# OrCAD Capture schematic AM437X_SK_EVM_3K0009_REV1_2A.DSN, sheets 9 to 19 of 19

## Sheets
9 Pg03: Processor Power: size C
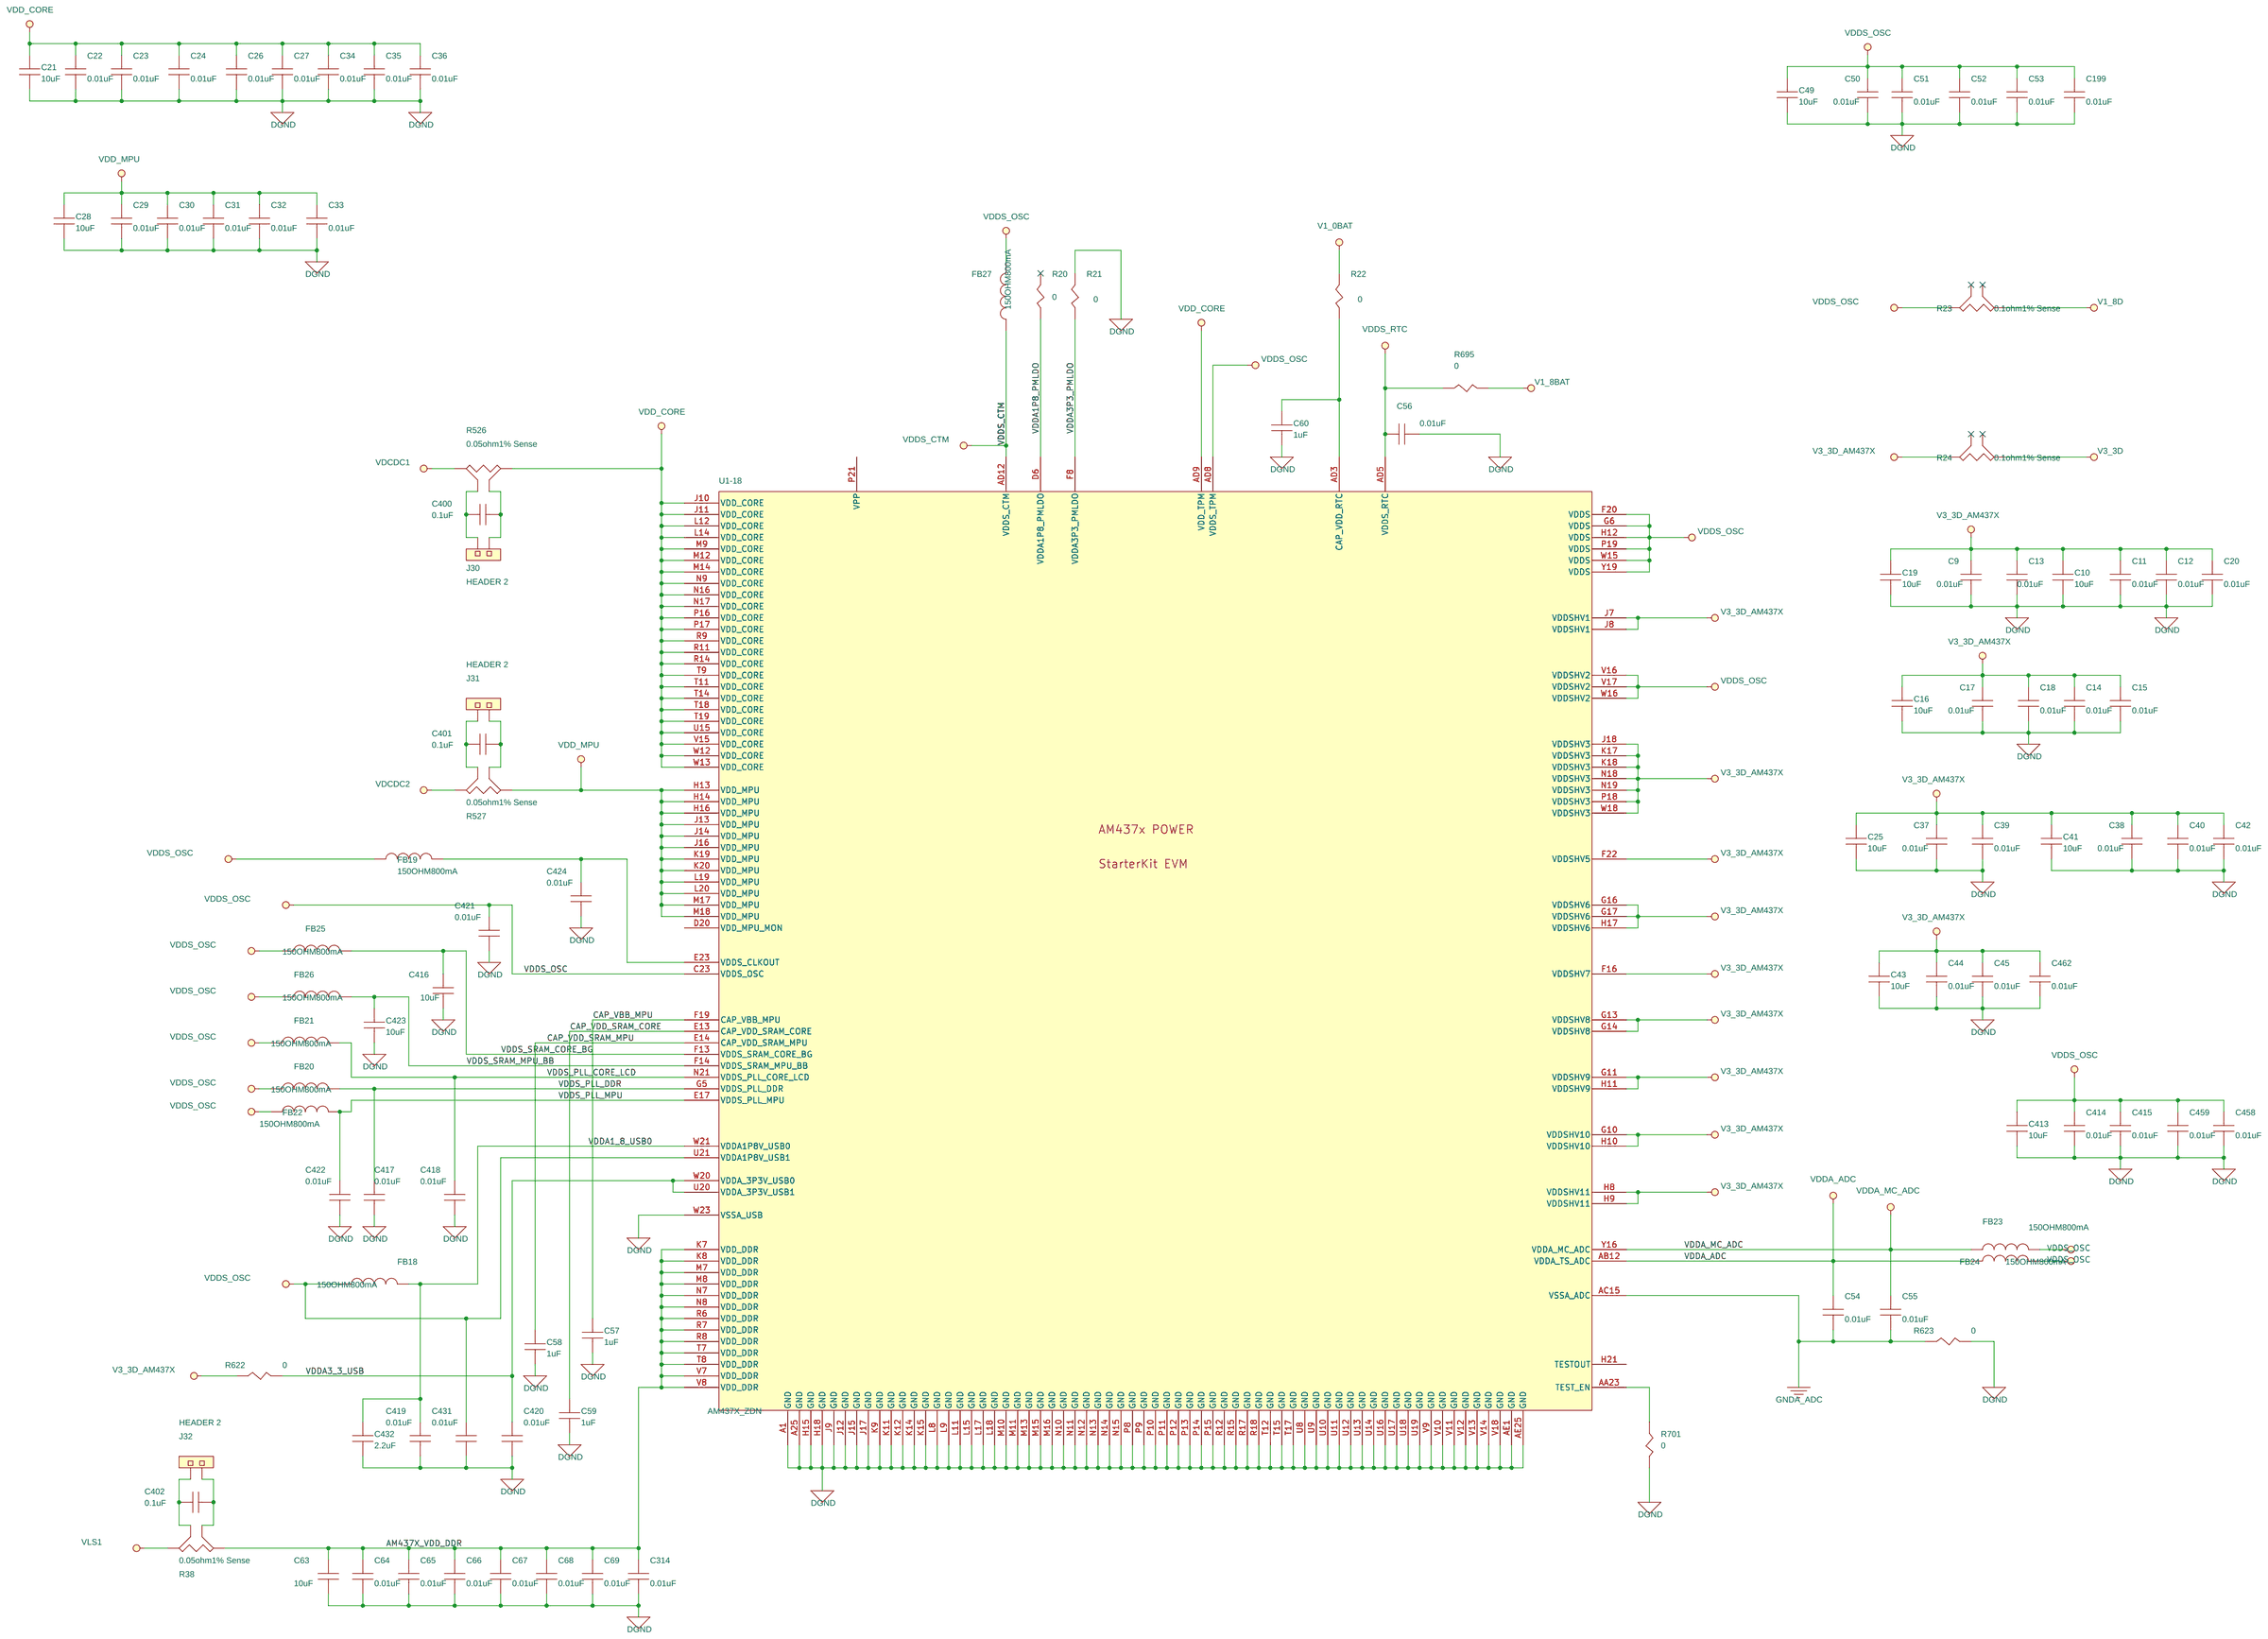
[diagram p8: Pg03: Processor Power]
10 Pg14: USB Port #1: size C
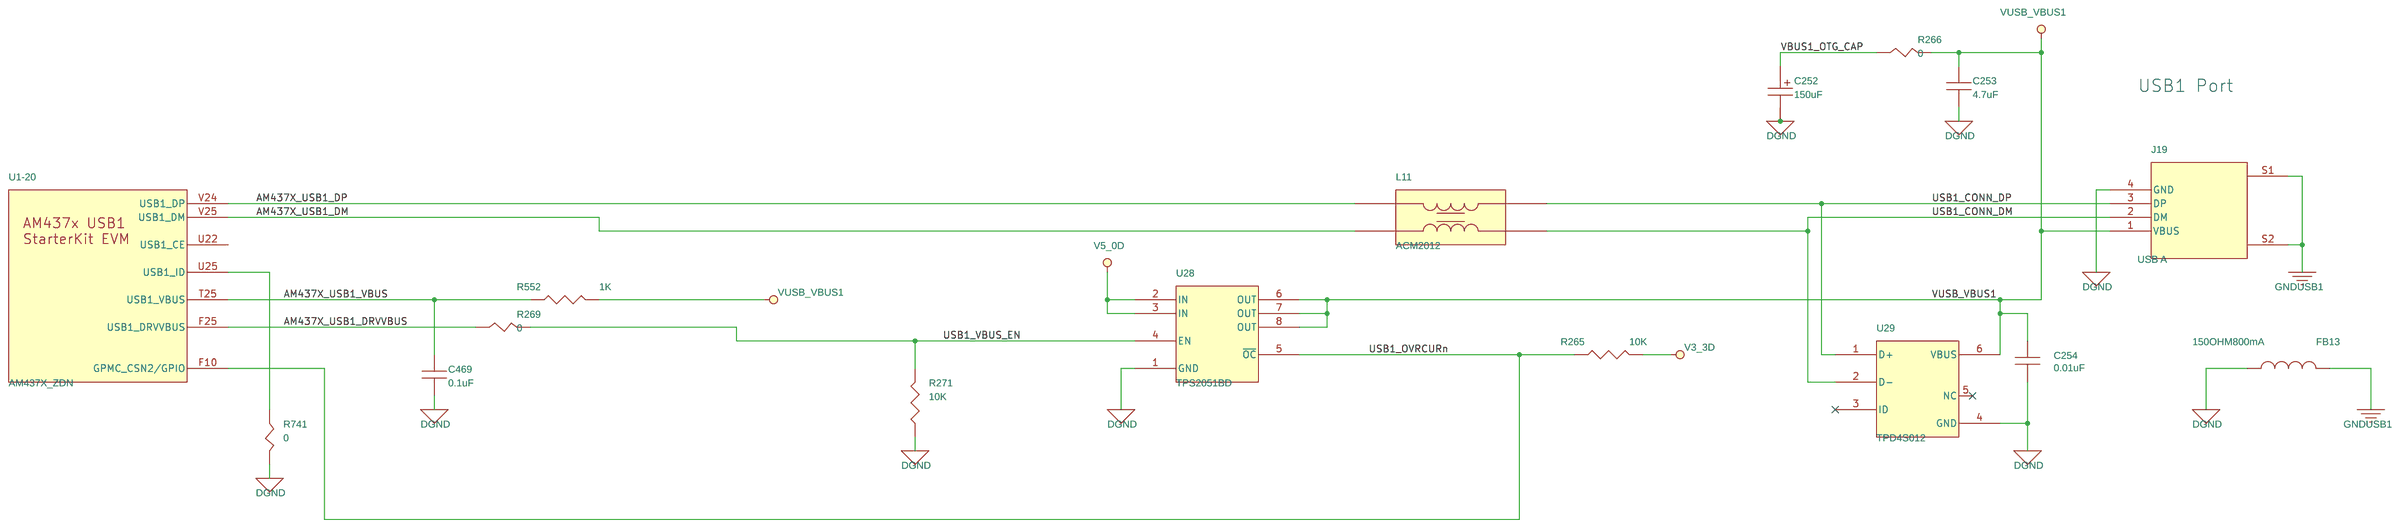
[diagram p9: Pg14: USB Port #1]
11 Pg13: USB Port #0: size C
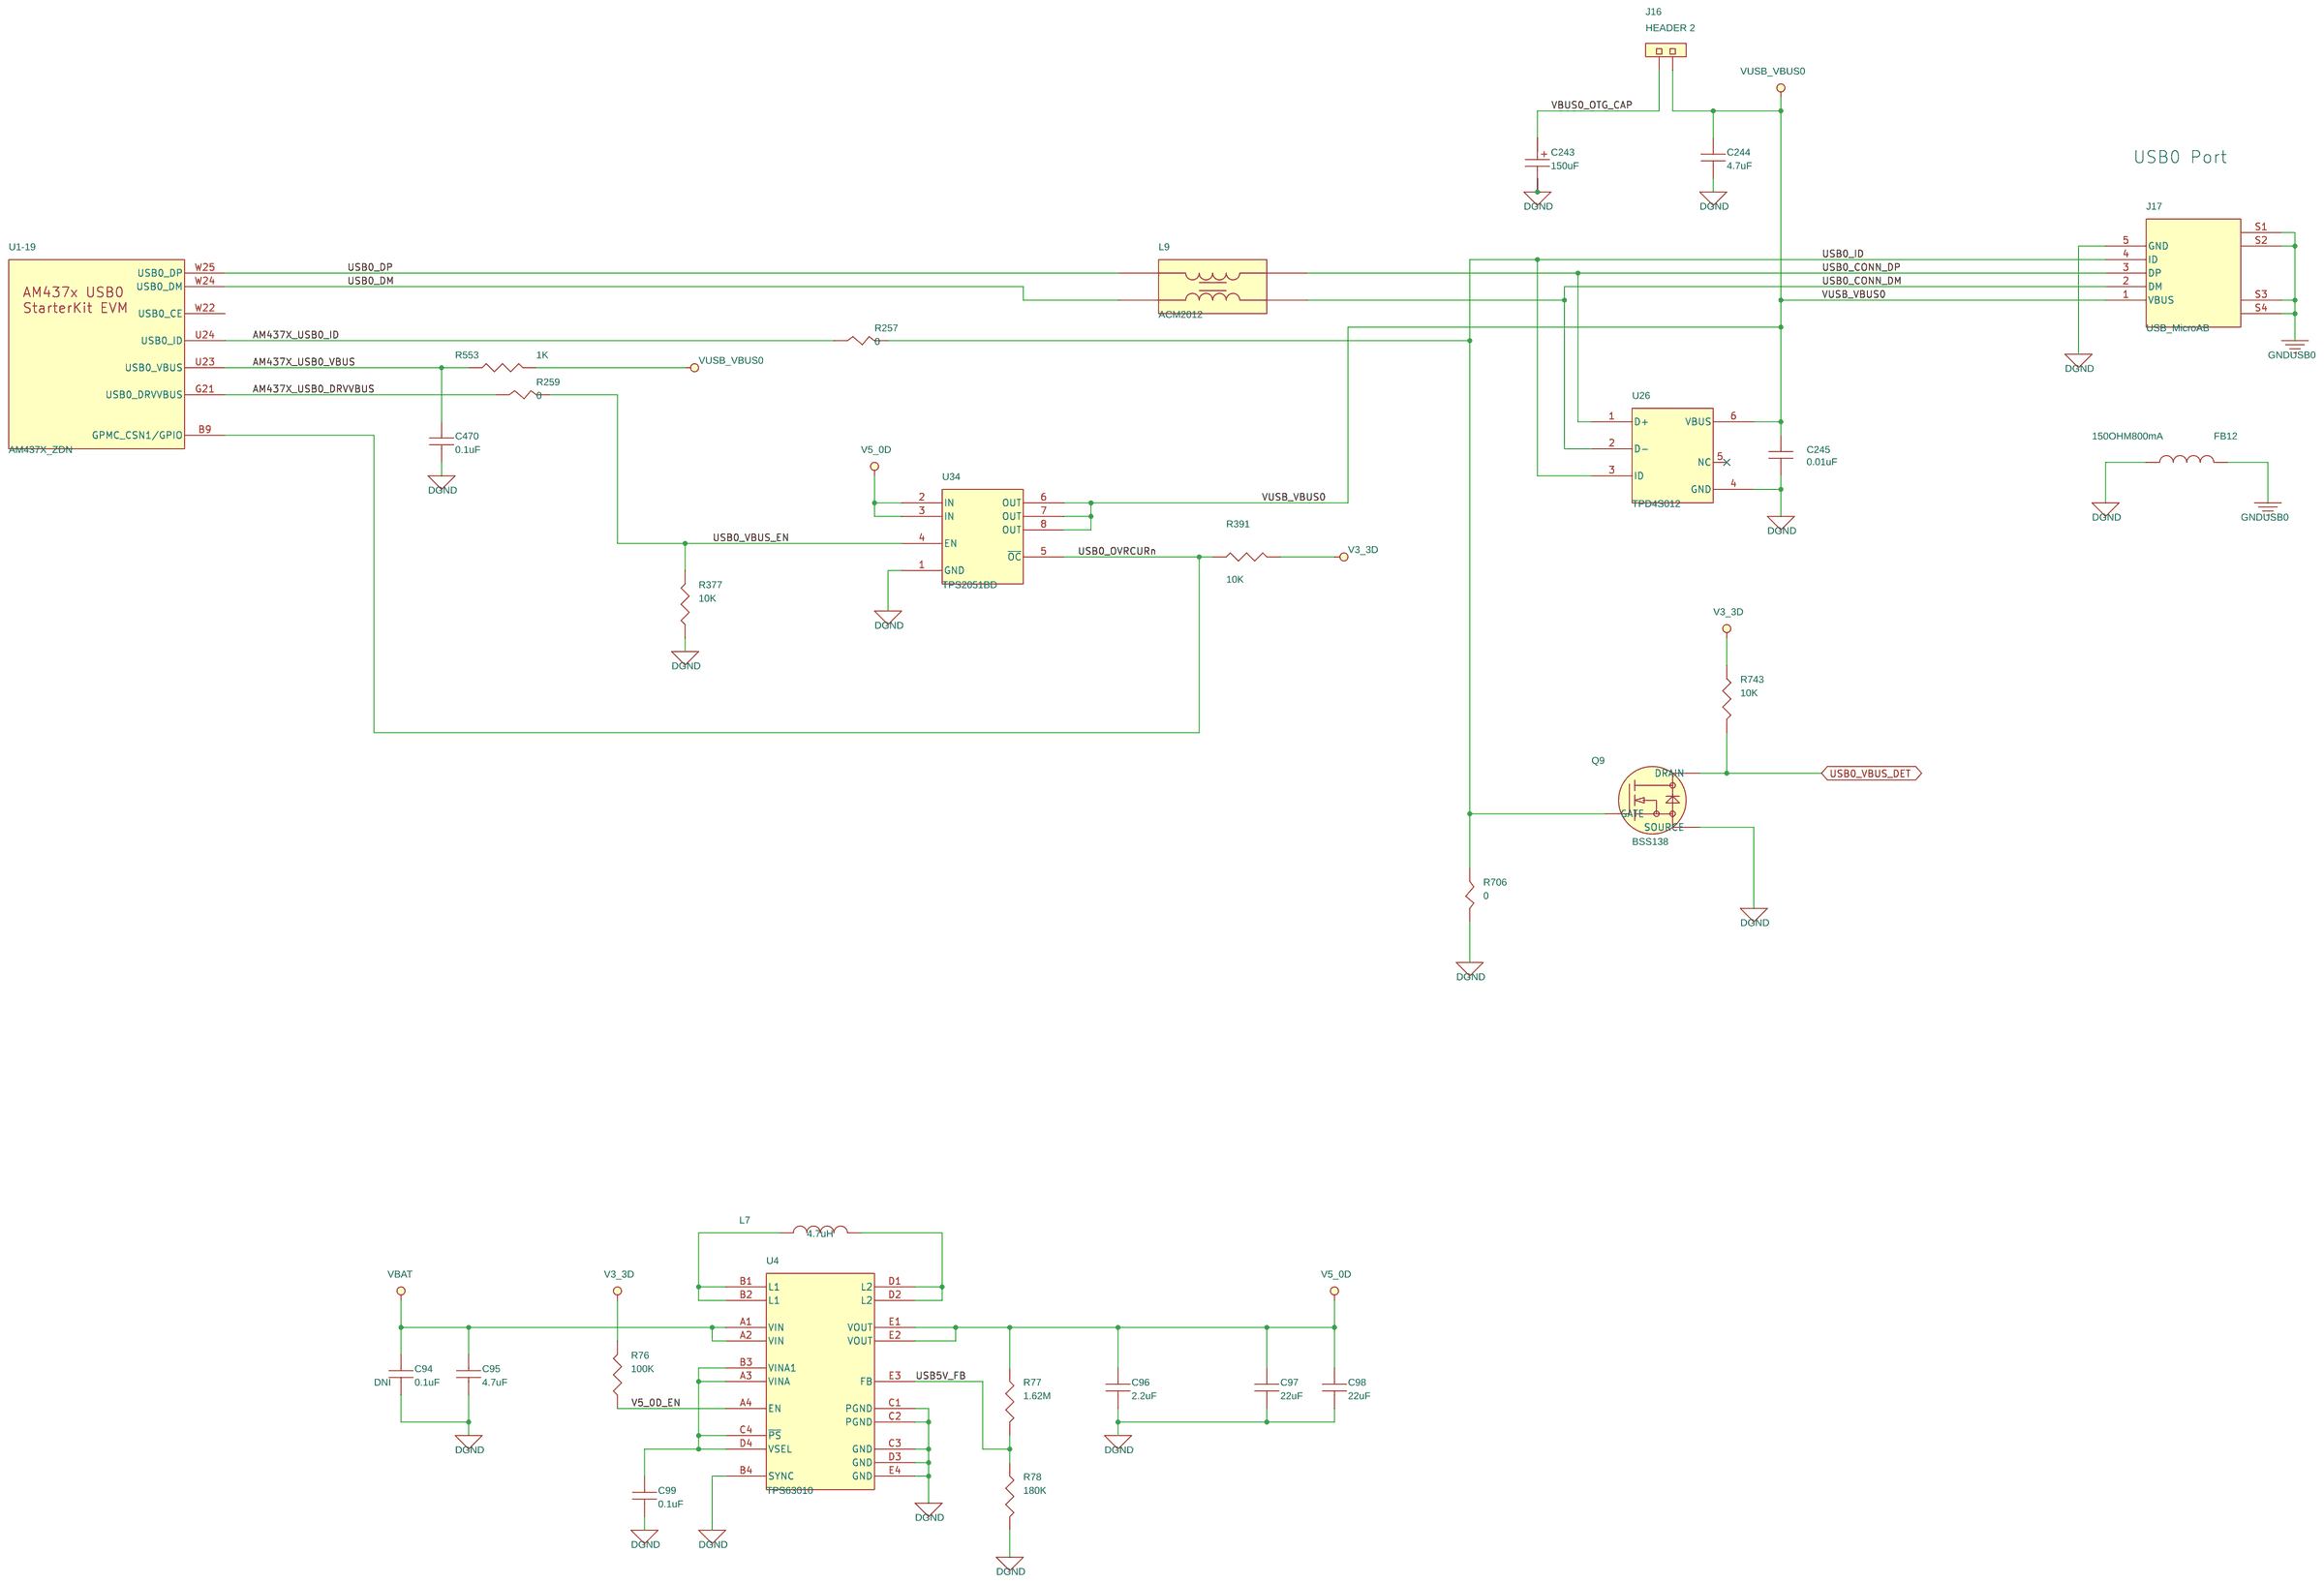
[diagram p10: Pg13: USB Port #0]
12 Pg17: Keypad/LED's: size C
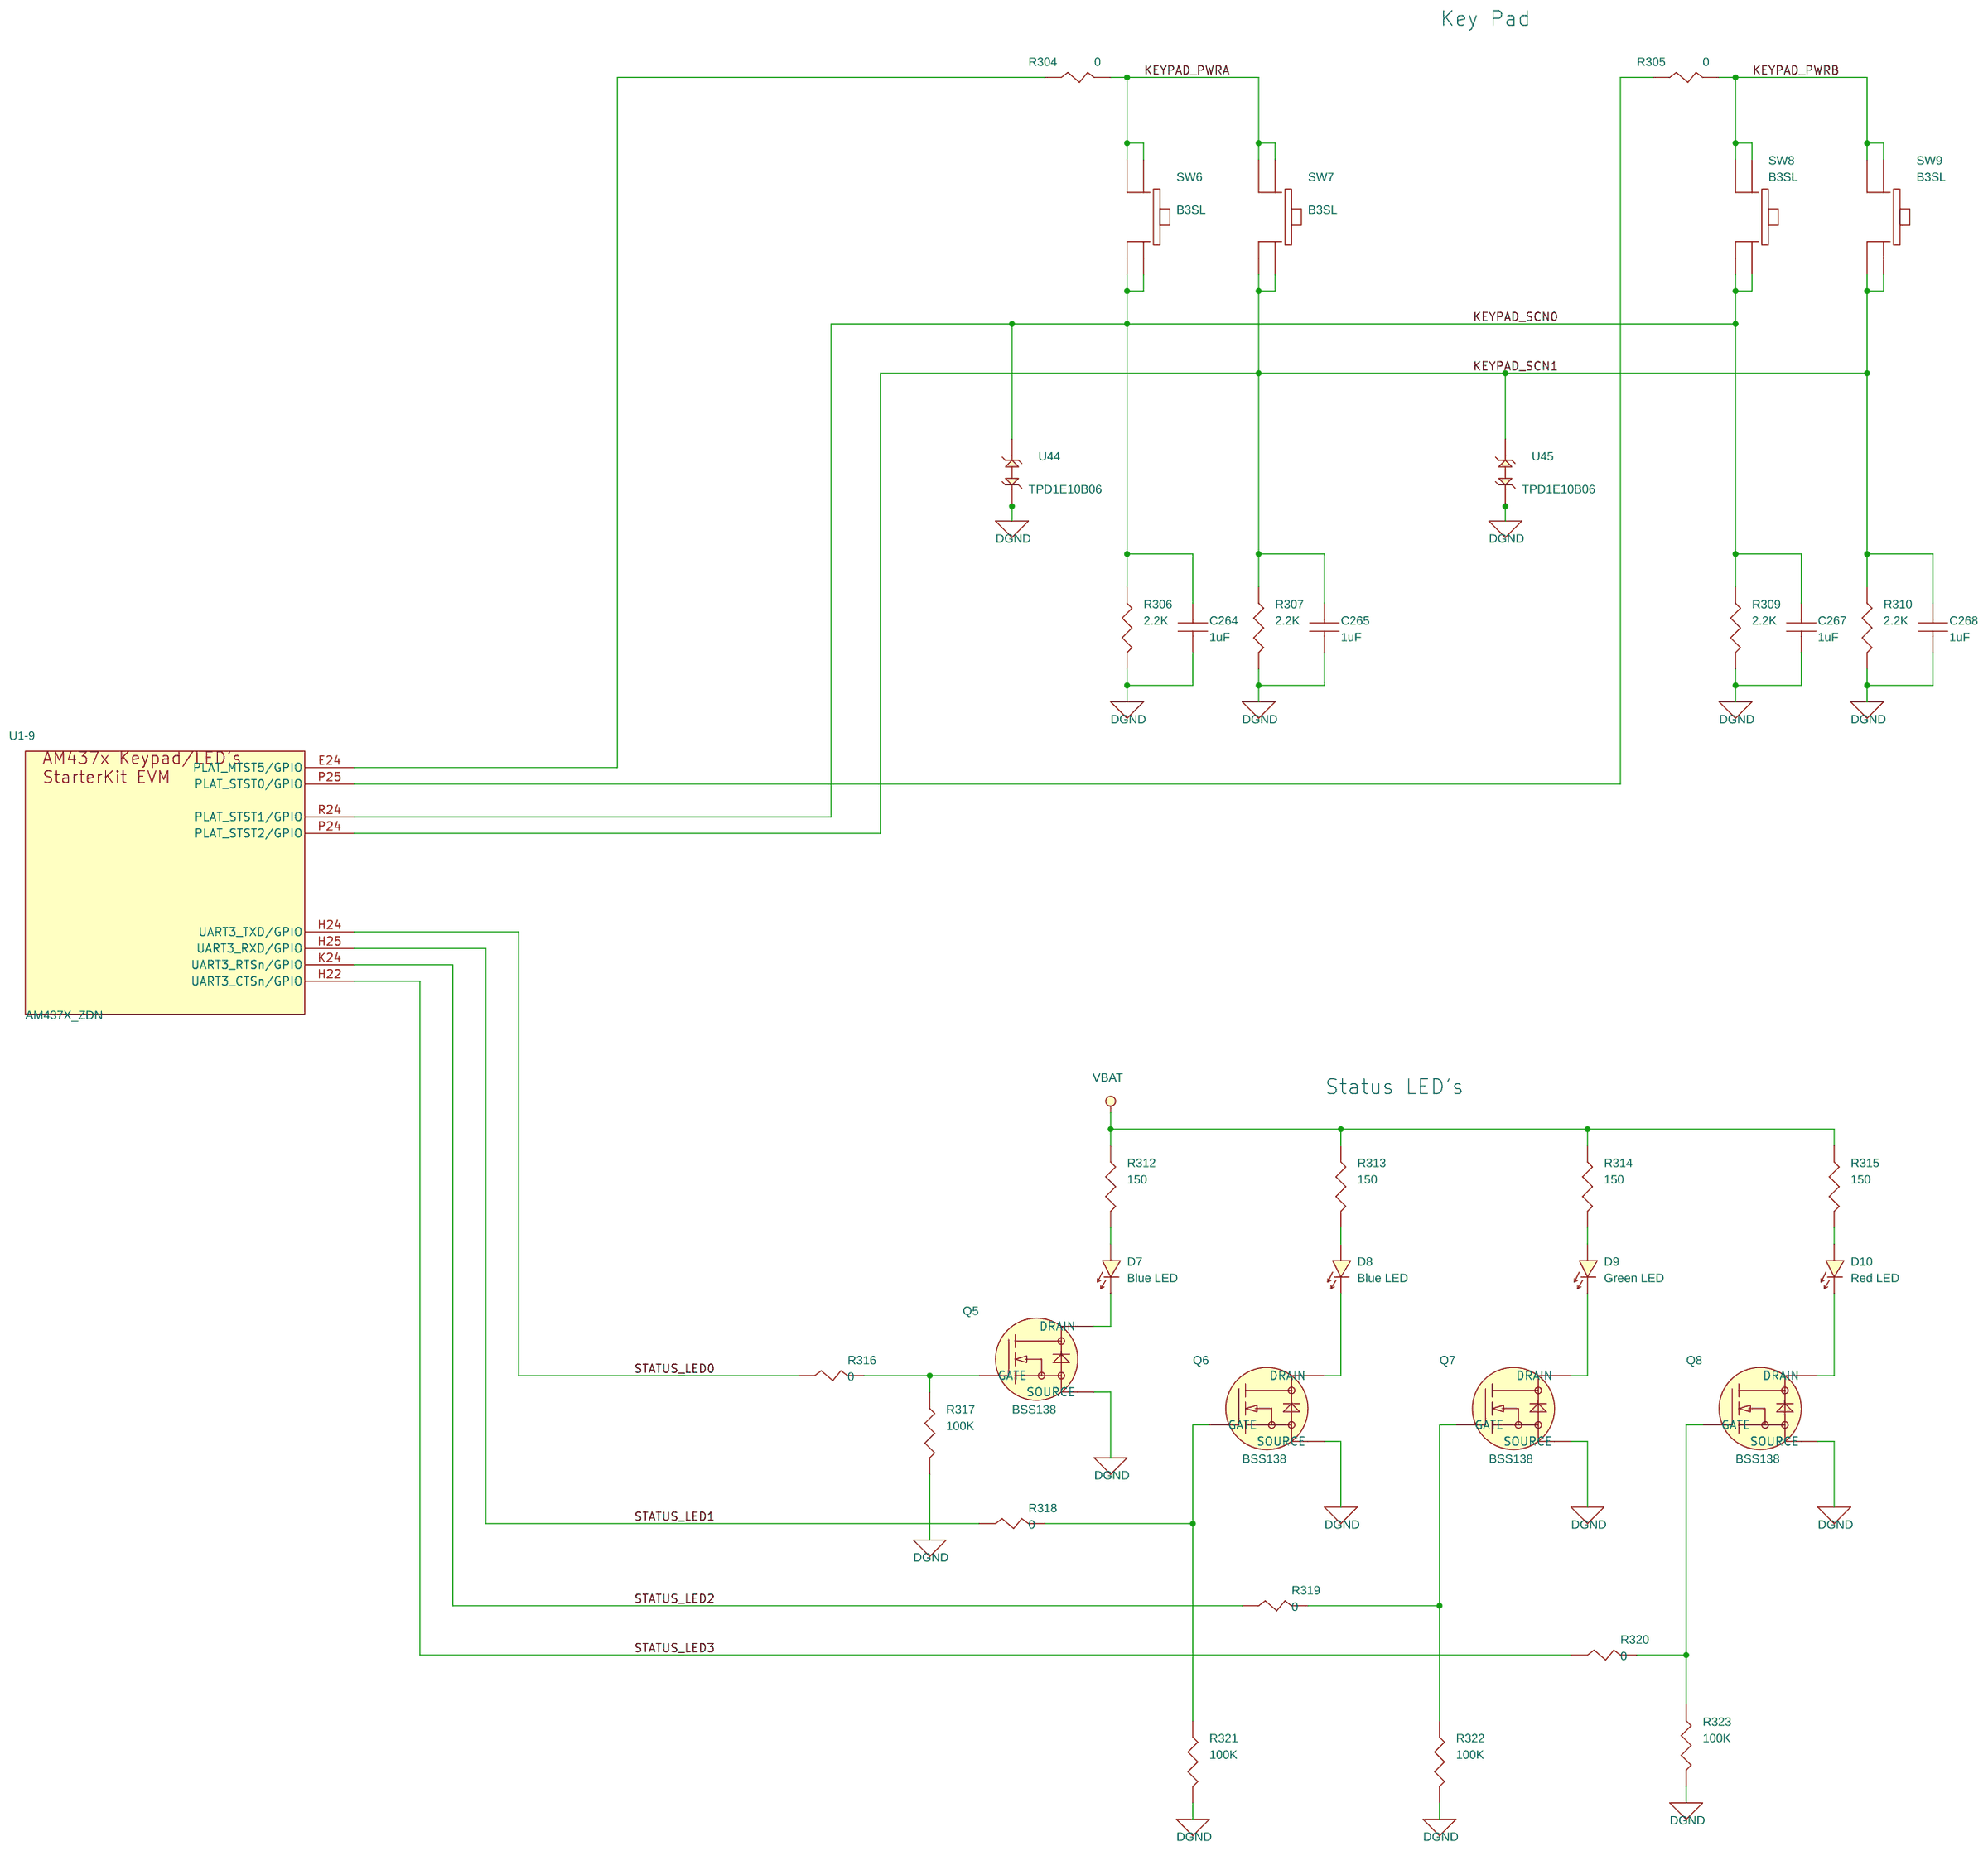
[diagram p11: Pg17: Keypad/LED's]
13 Pg07: SDMMC0 Interface: size C
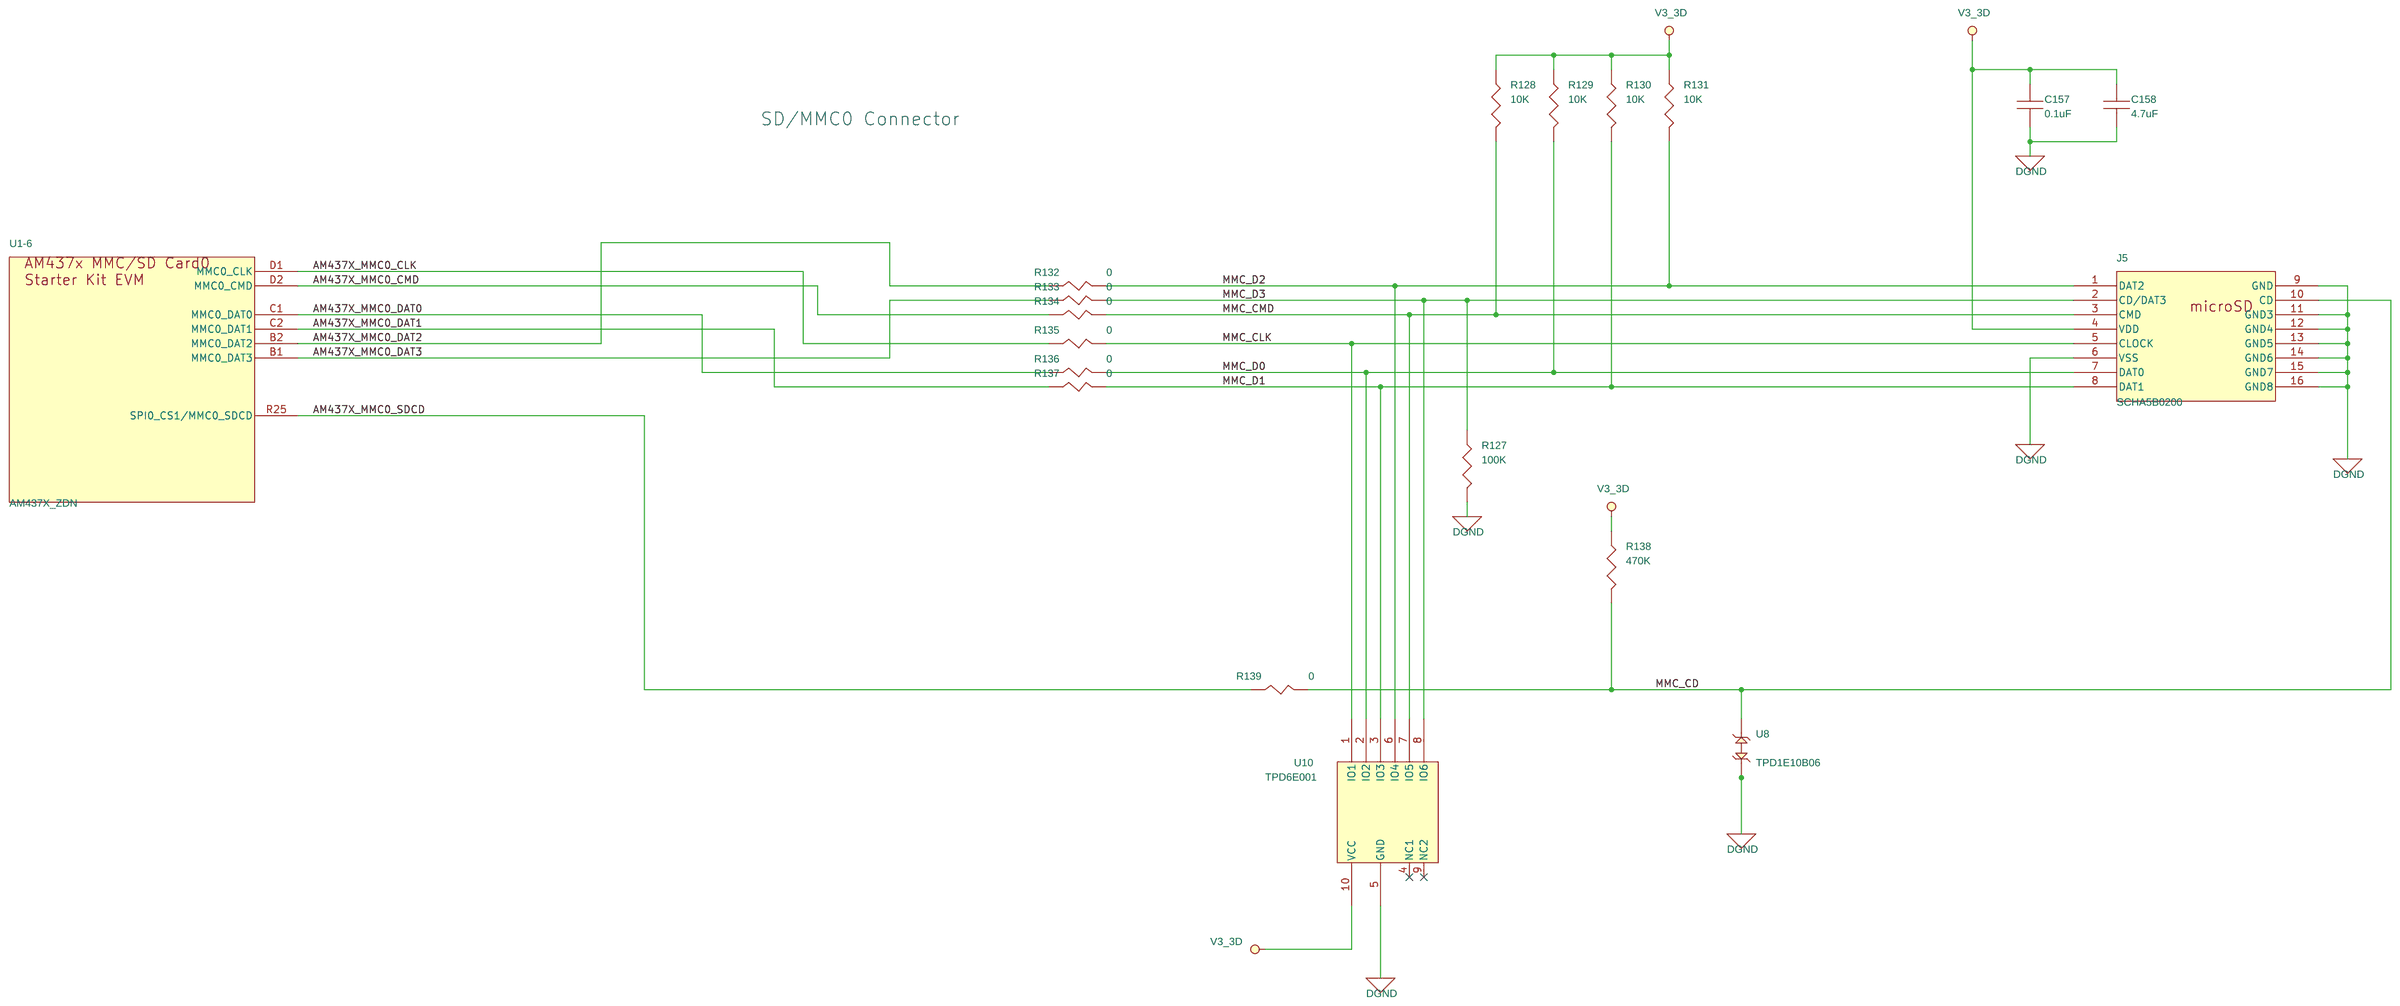
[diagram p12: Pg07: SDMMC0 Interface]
14 Pg11: LCD/Touchscreen: size C
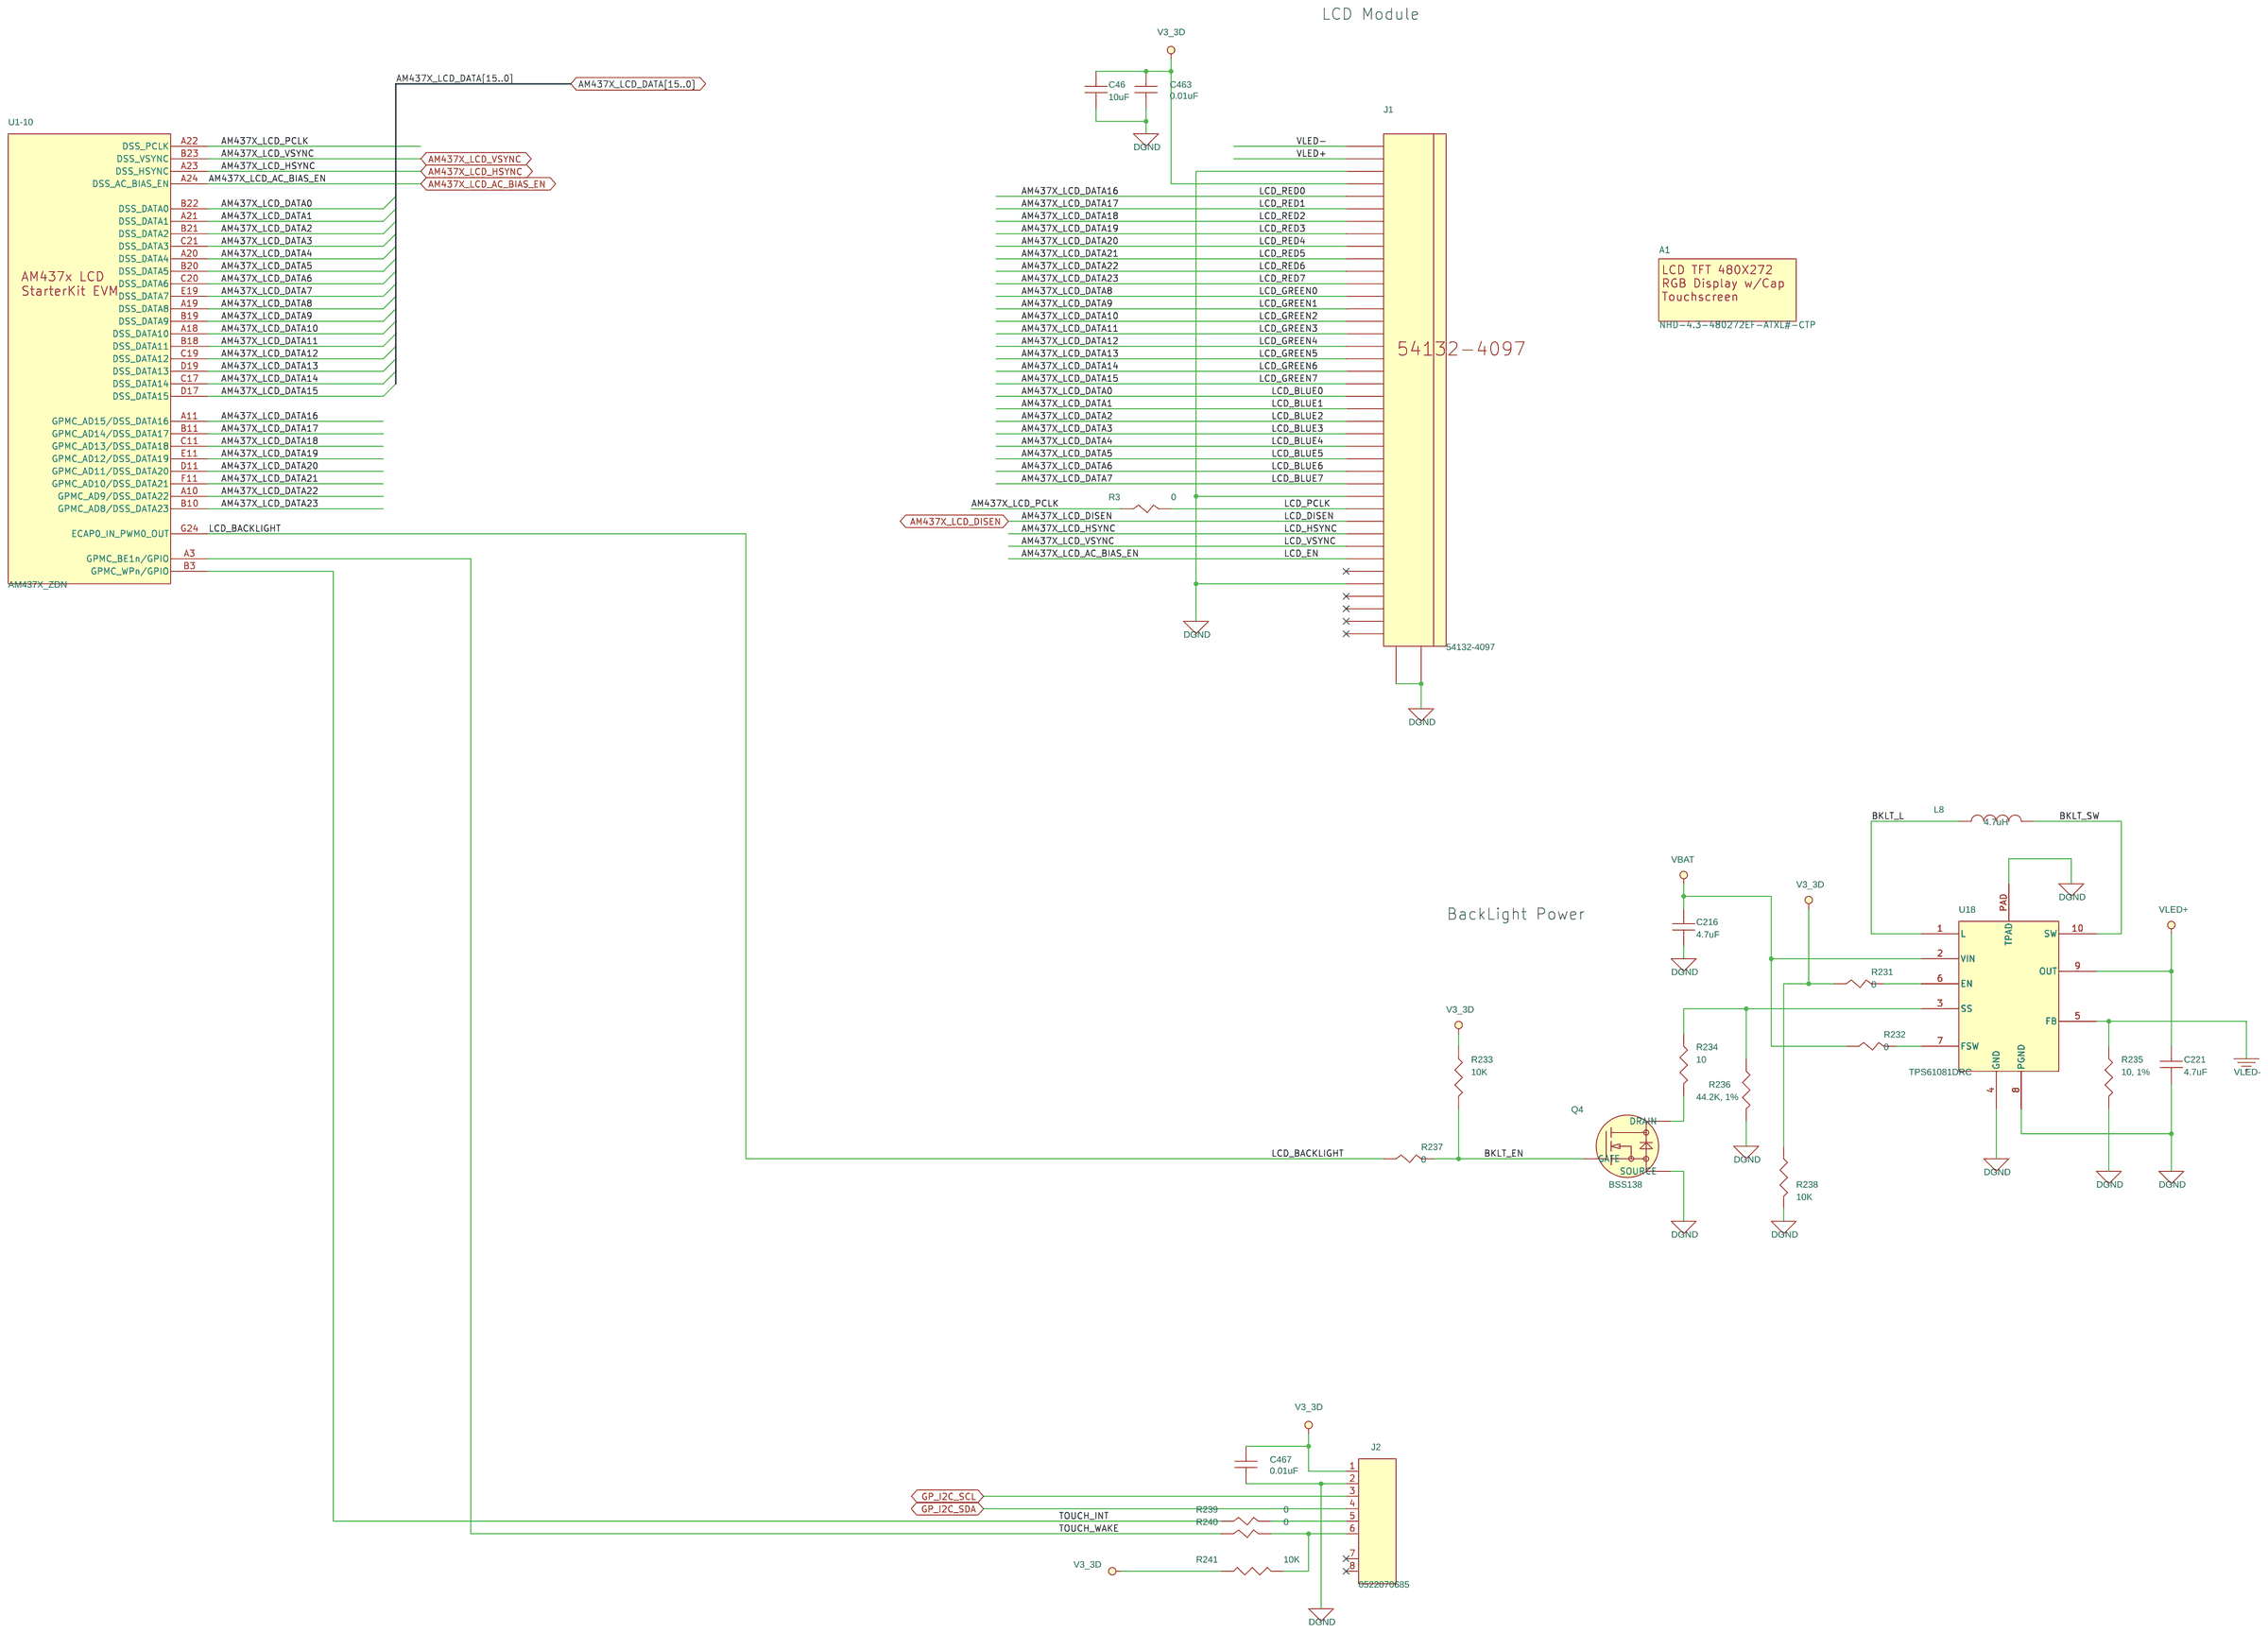
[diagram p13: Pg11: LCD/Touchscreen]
15 Pg02: Processor subsystem: size C
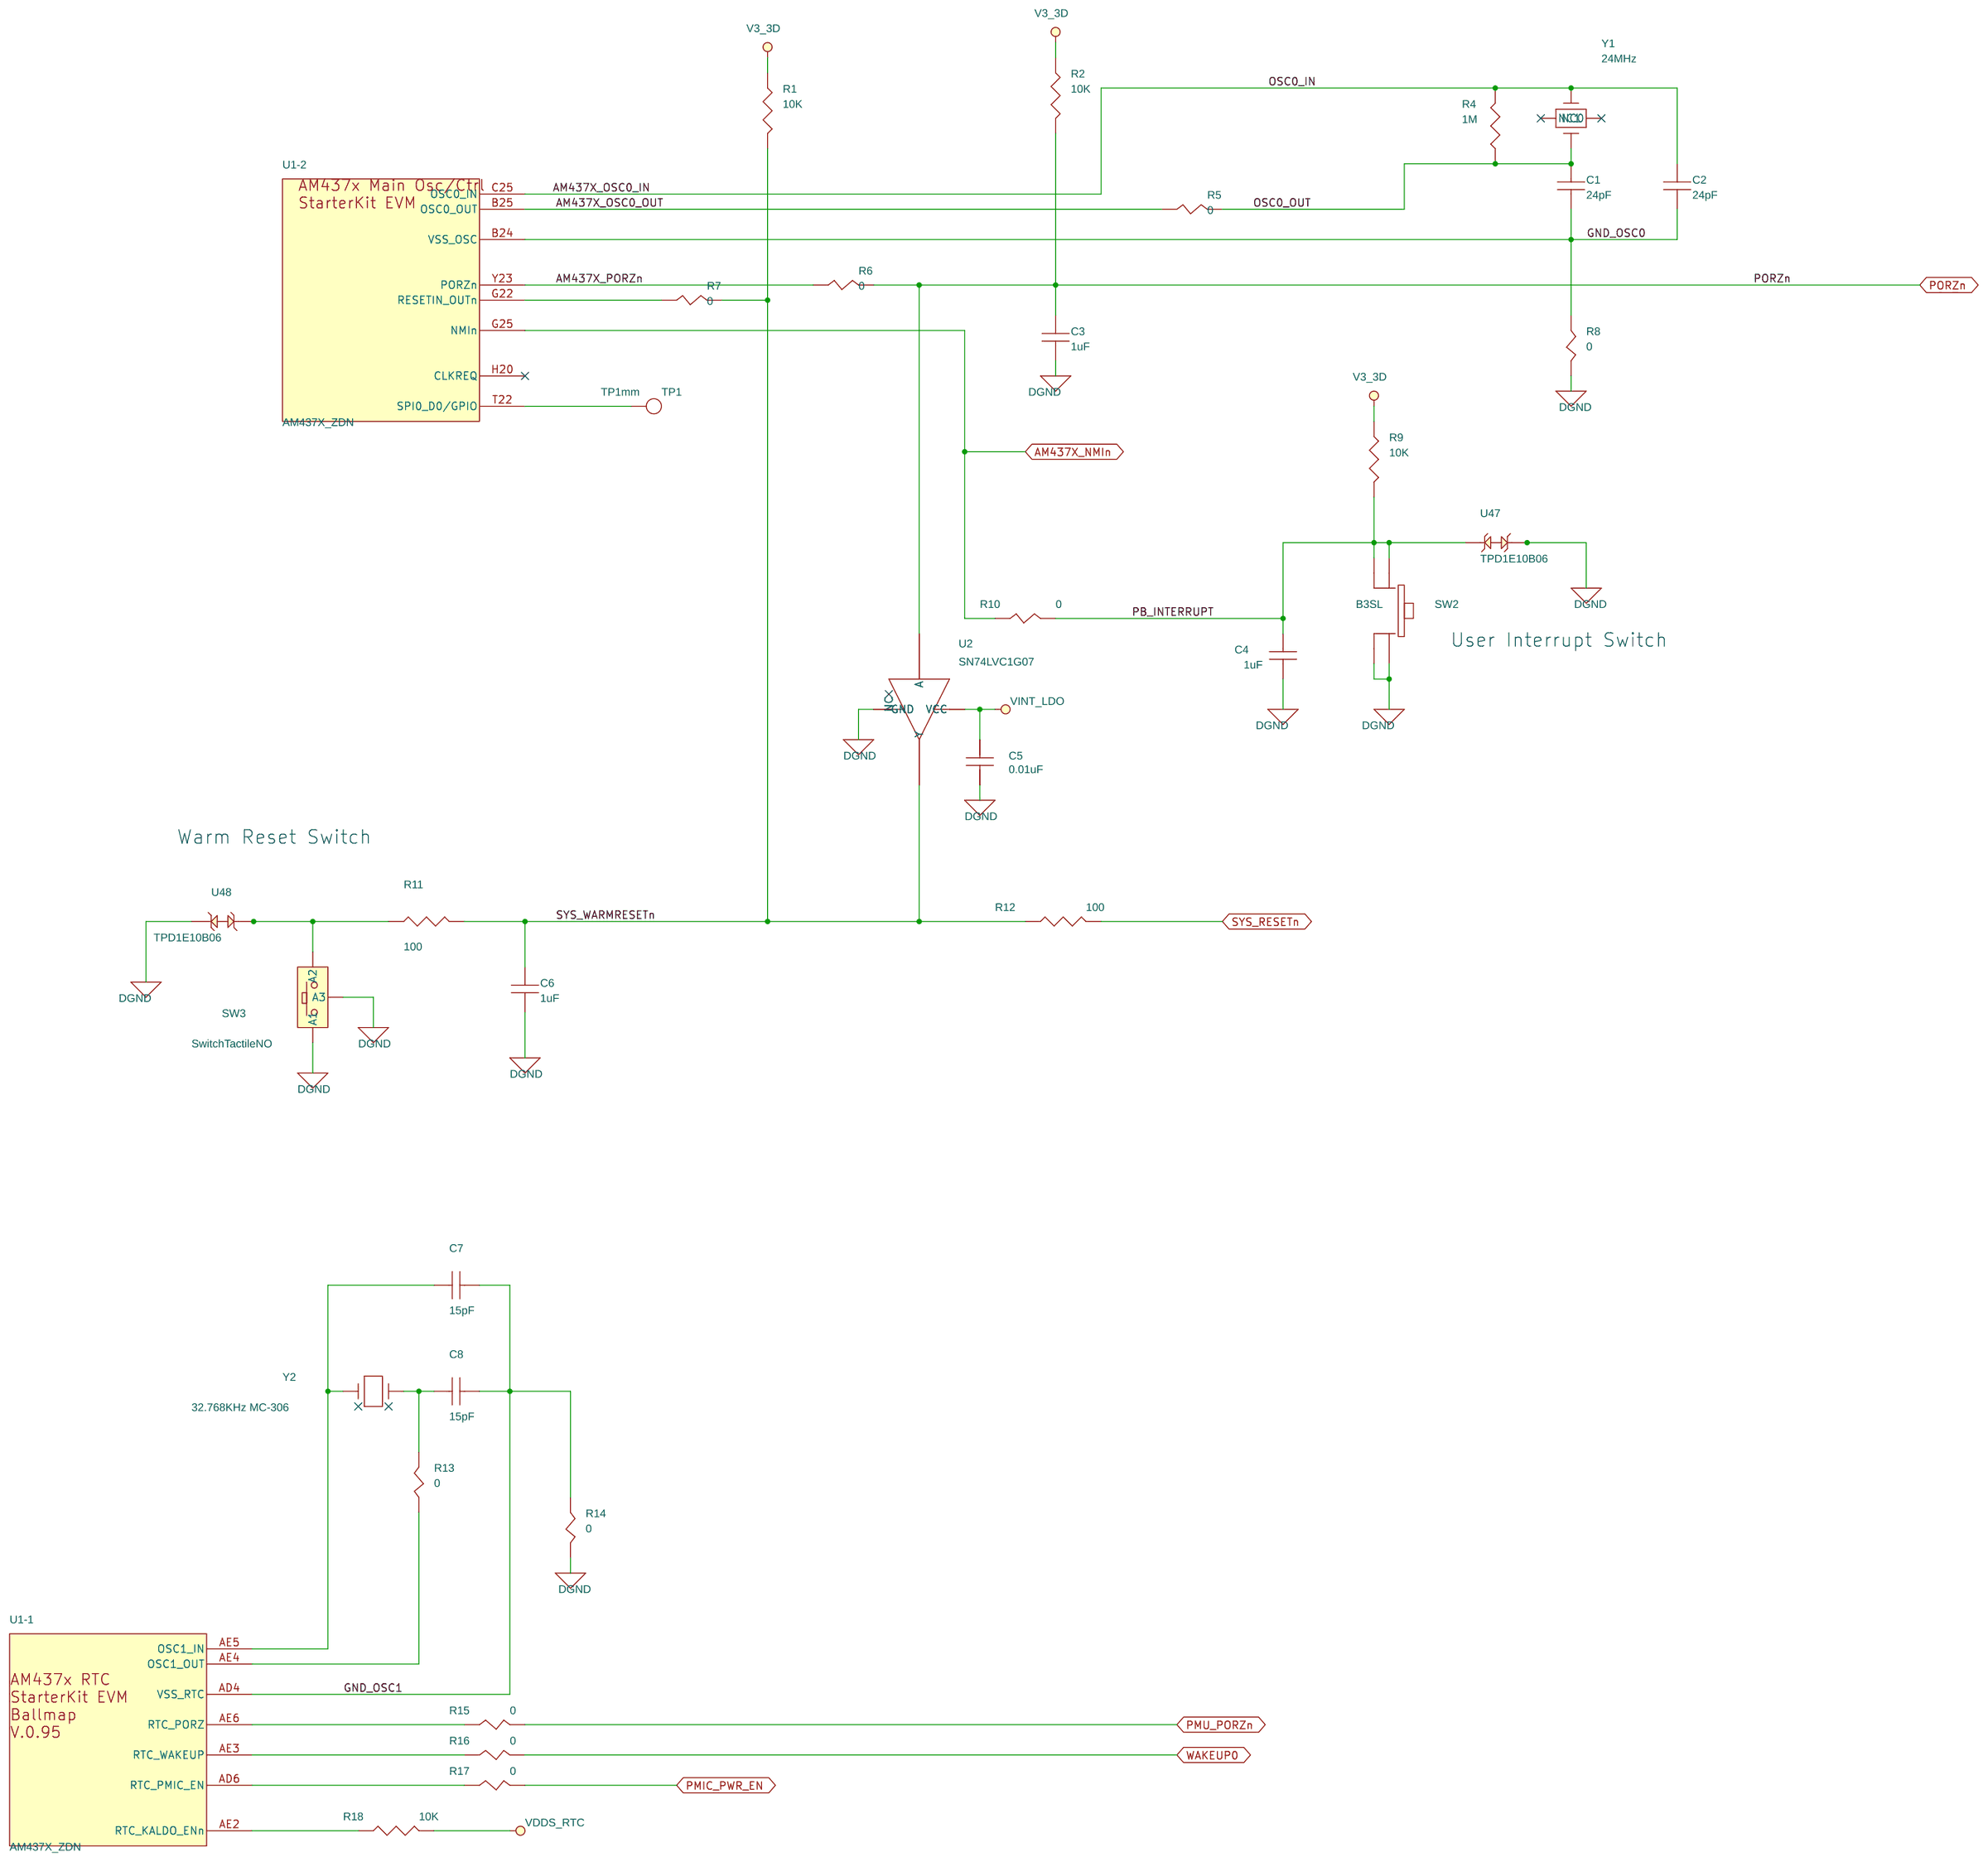
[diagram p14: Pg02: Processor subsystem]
16 Pg15: Unused pins/GPIO: size C
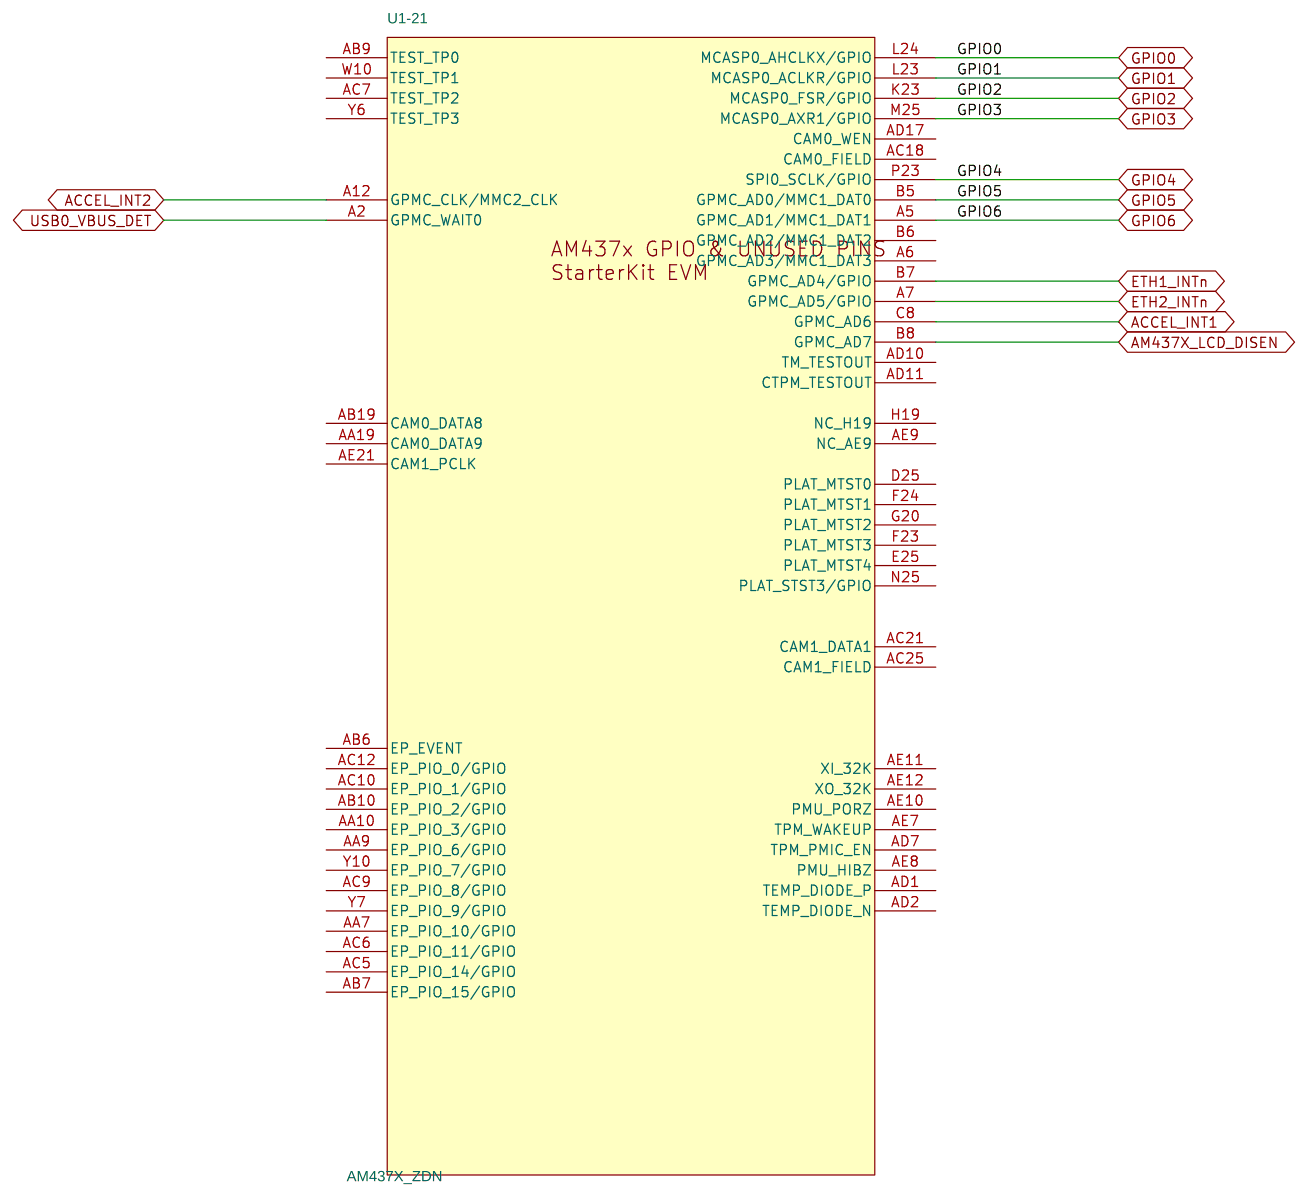
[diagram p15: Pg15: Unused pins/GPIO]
17 Pg05: QSPI NOR Flash Memory: size C
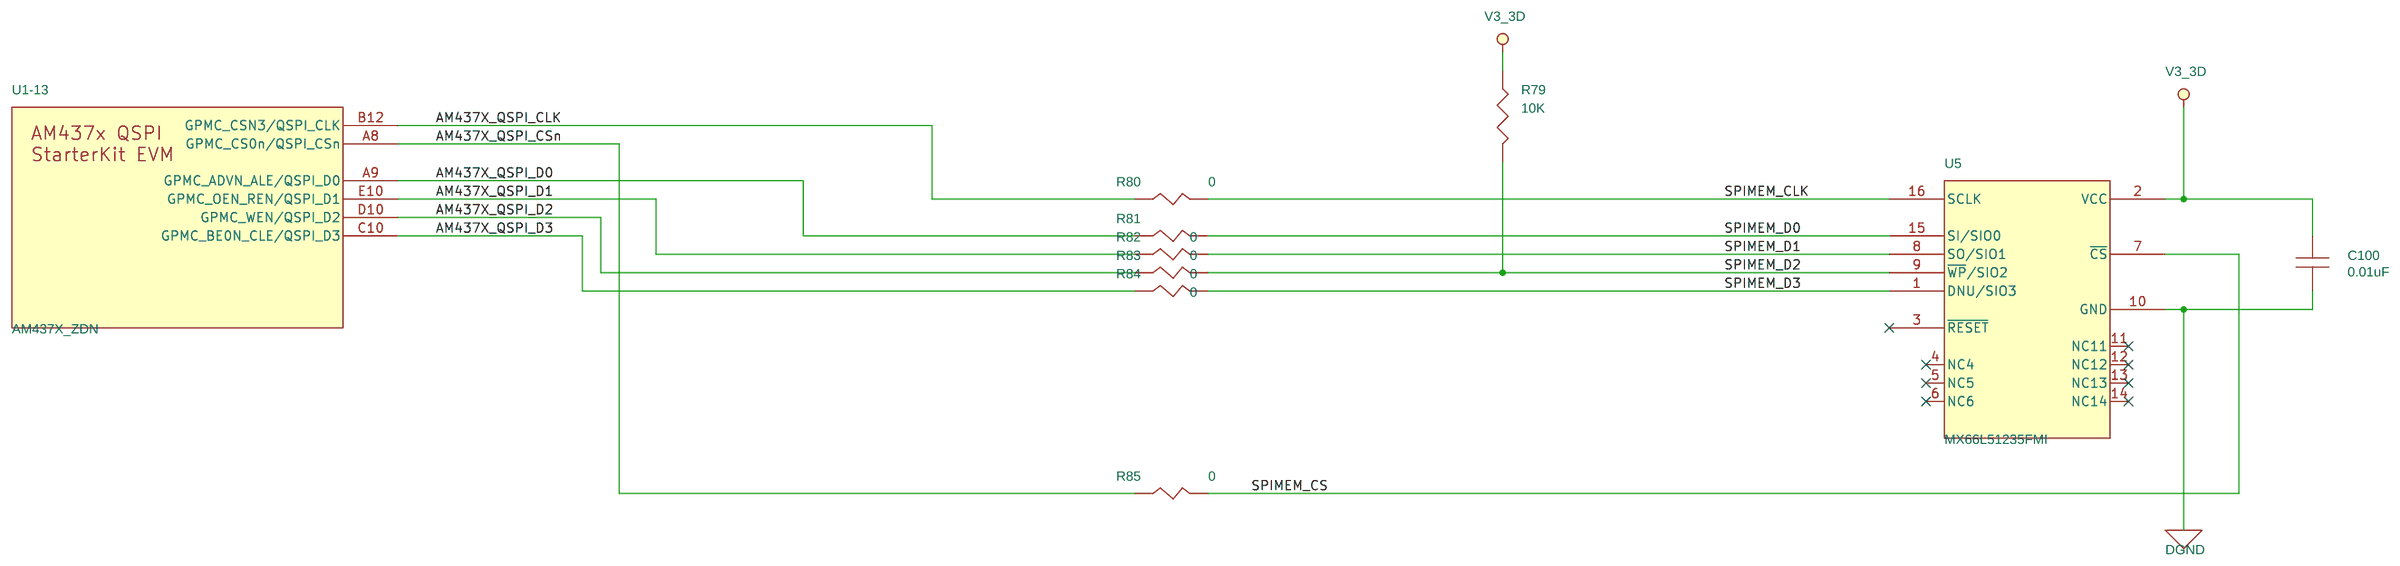
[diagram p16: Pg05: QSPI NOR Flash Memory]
18 Pg04: Power Supply - PMIC: size C
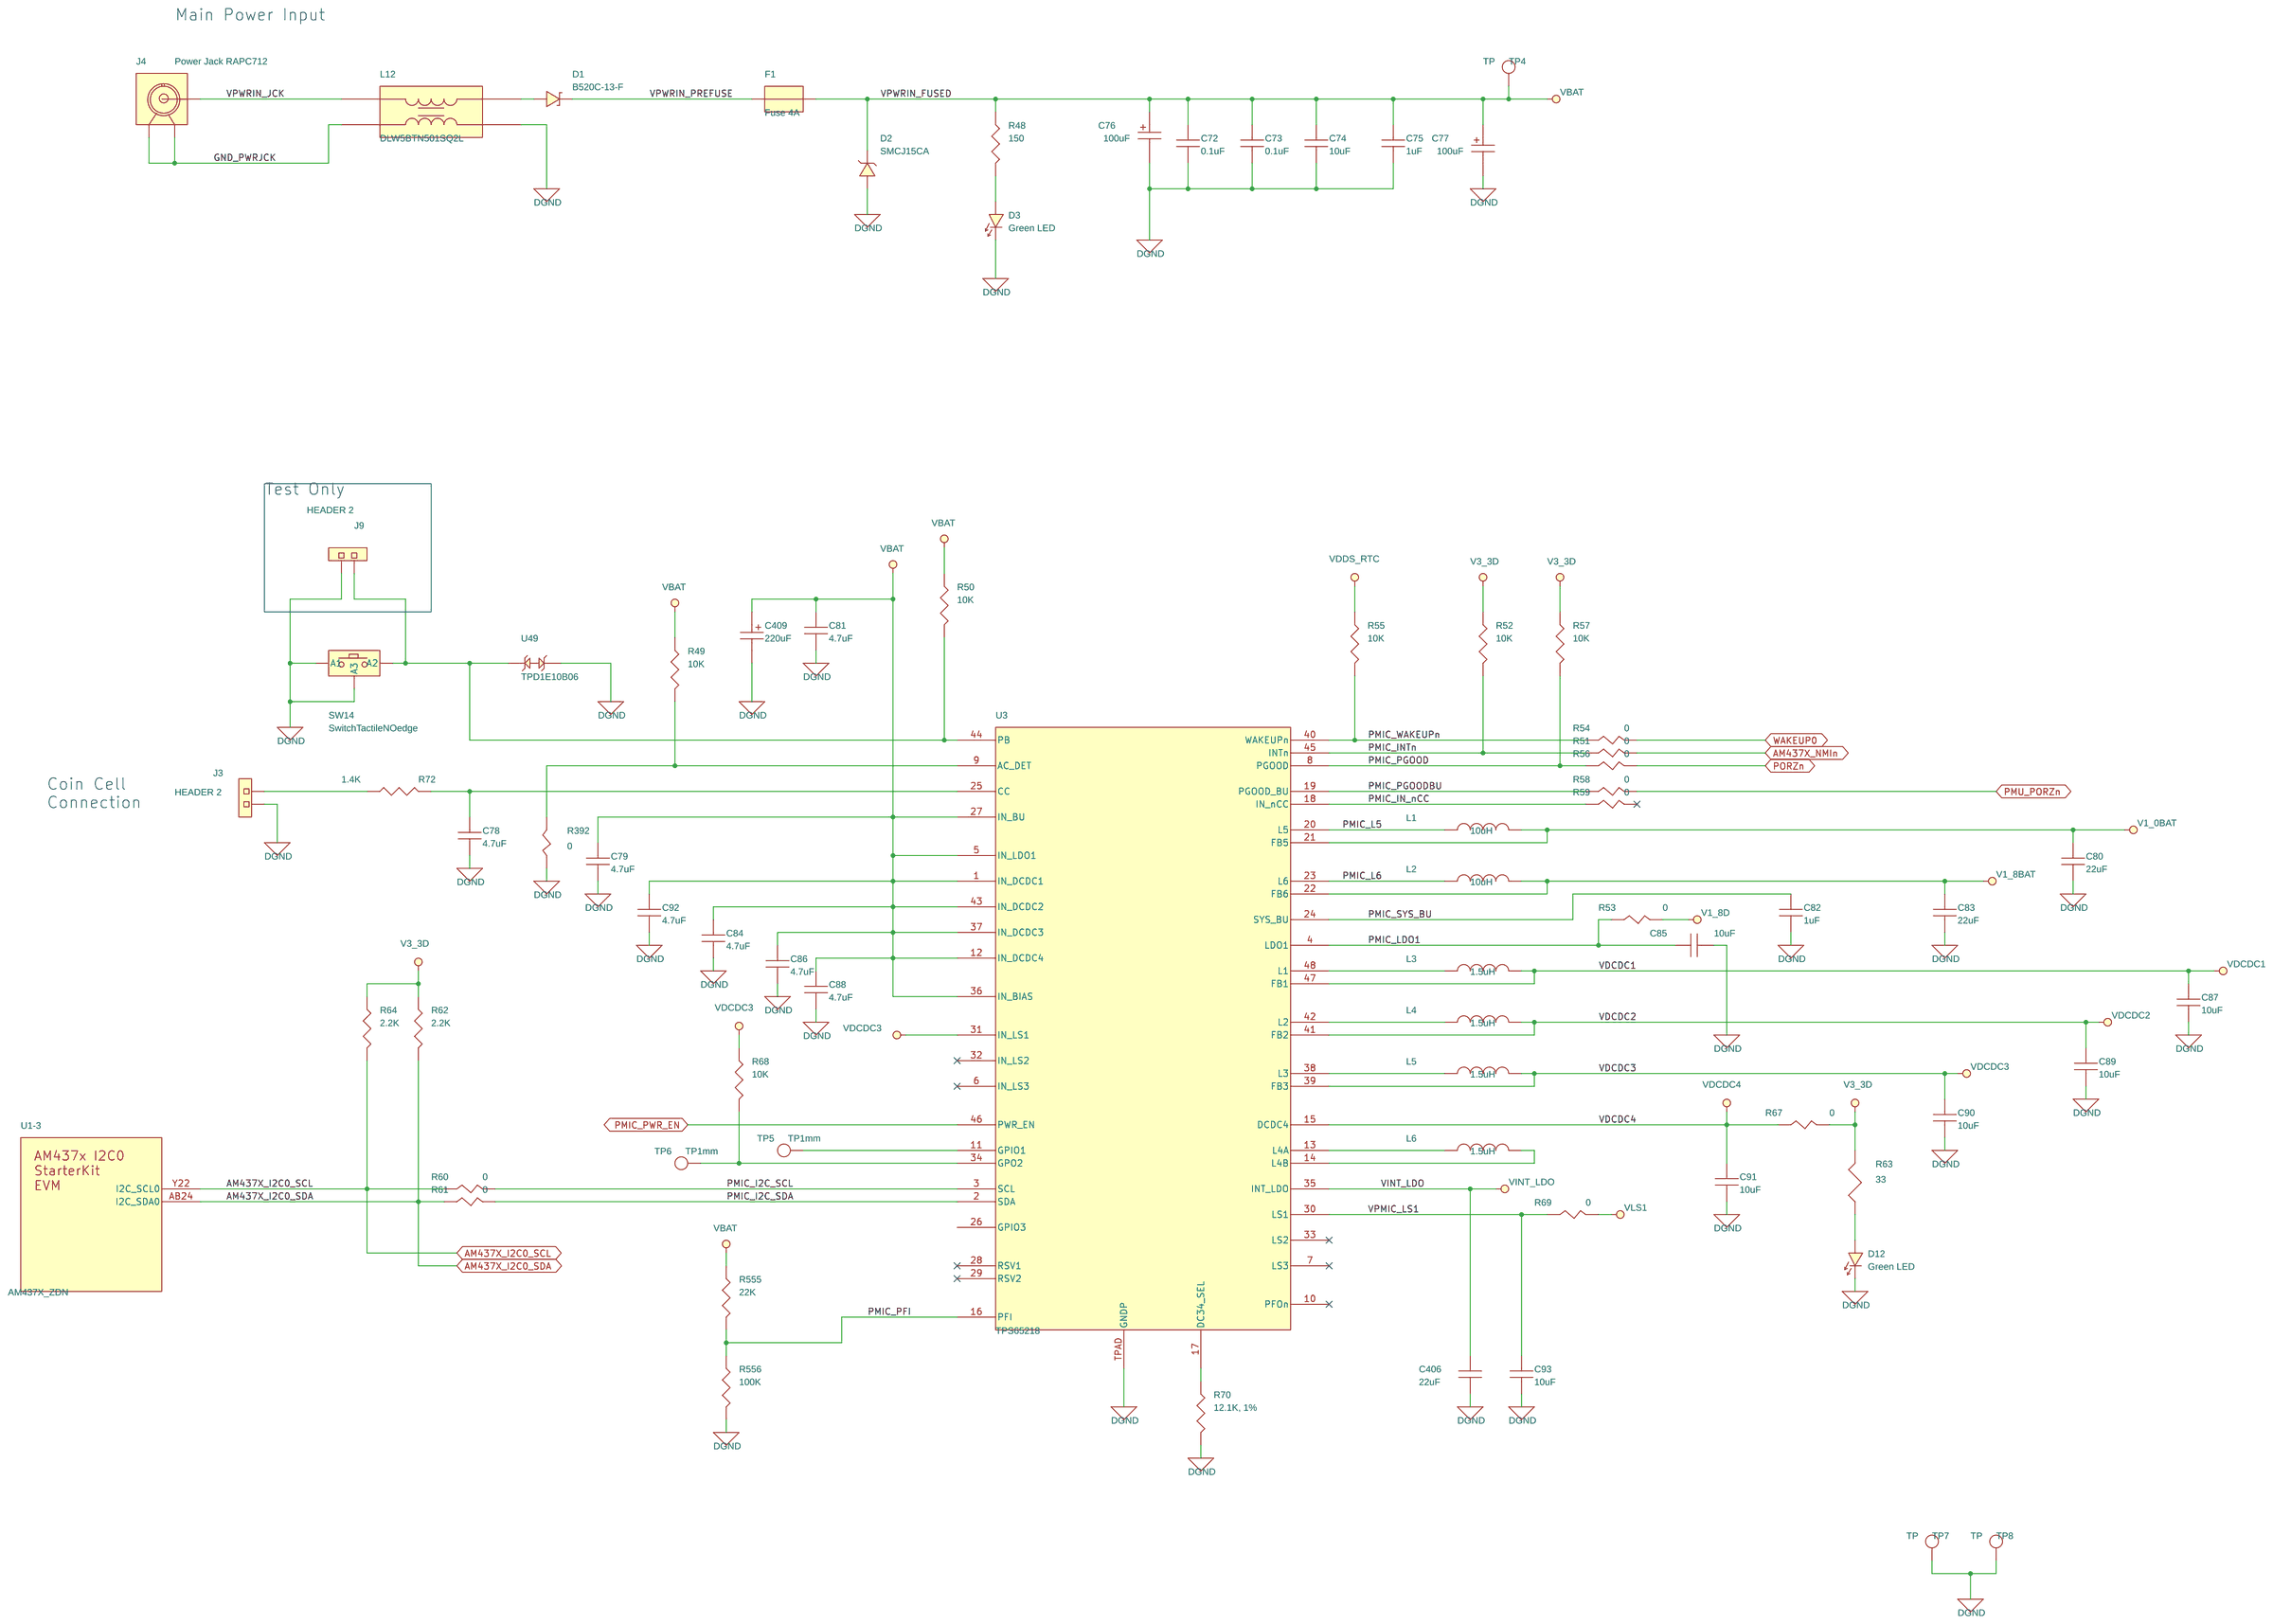
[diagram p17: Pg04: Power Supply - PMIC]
19 Pg16: Wireless/Bluetooth WLink8: size C
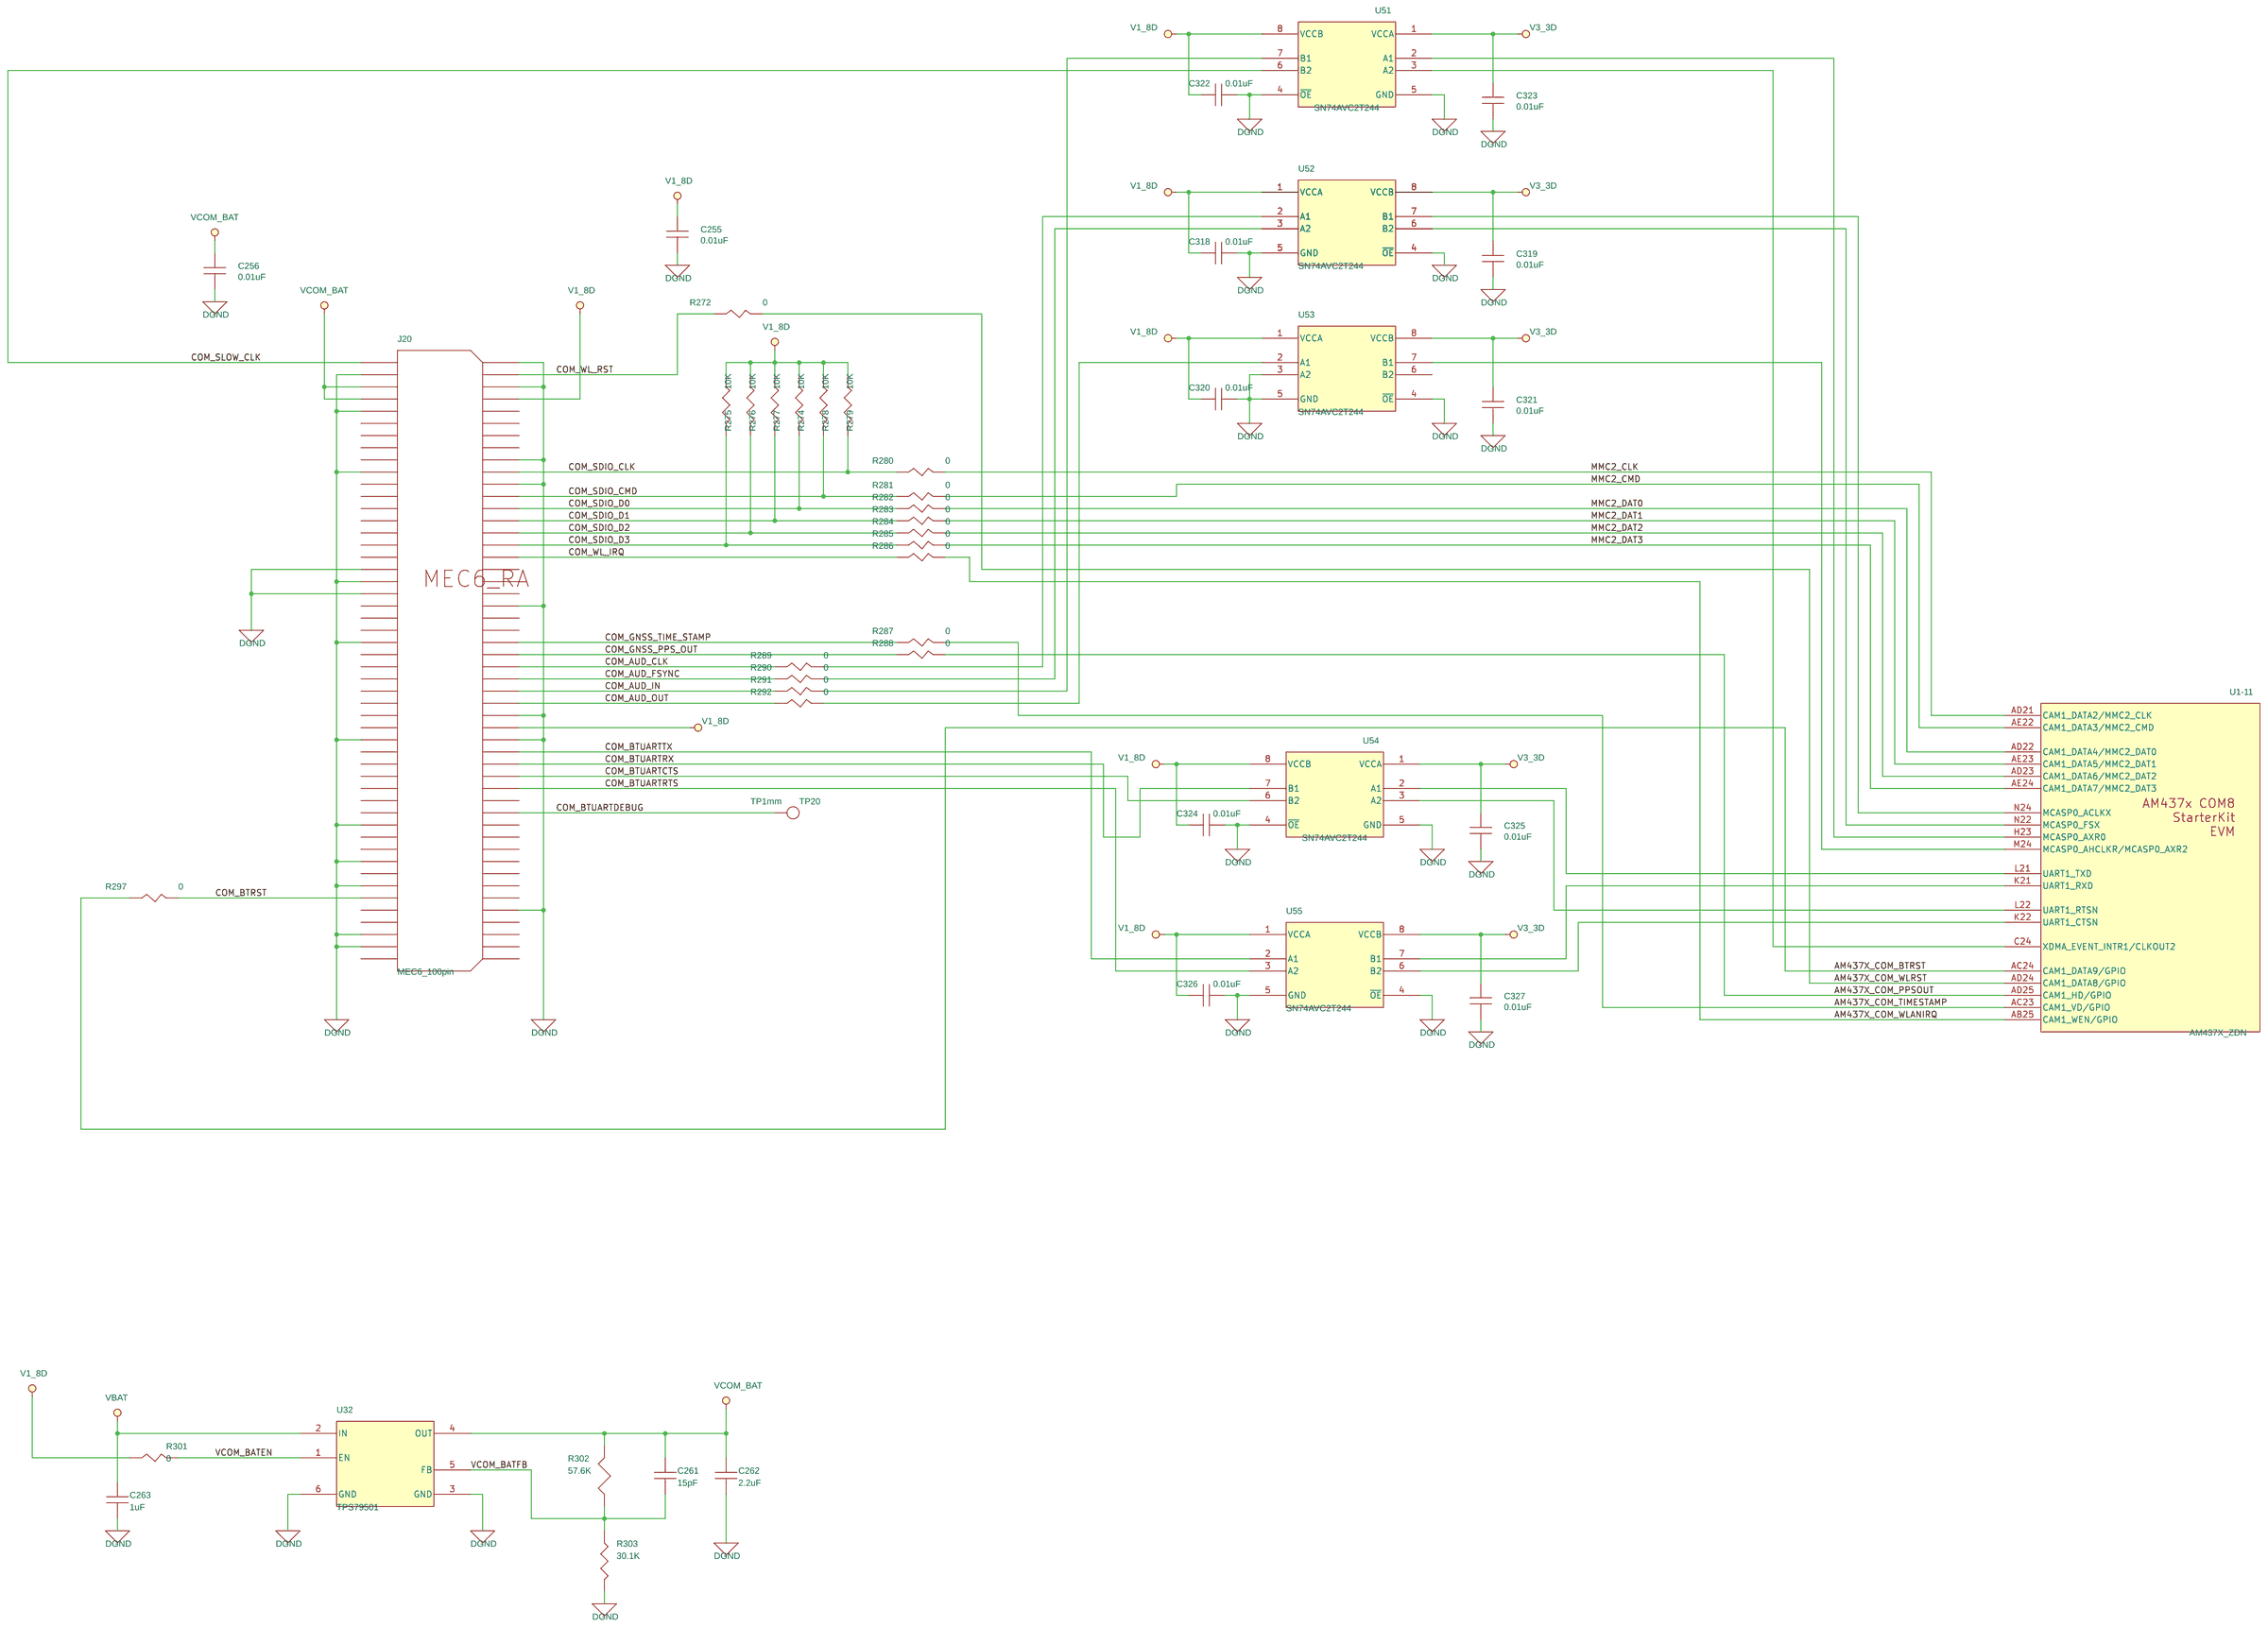
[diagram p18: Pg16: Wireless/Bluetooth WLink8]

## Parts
sheet Pg02: Processor subsystem
C1  24pF  [SM-7351-CAP-0402]
C2  24pF  [SM-7351-CAP-0402]
C3  1uF  [SM-7351-CAP-0402]
C4  1uF  [SM-7351-CAP-0402]
C5  0.01uF  [SM-7351-CAP-0402]
C6  1uF  [SM-7351-CAP-0402]
C7  15pF  [SM-7351-CAP-0402]
C8  15pF  [SM-7351-CAP-0402]
R1  10K  [SM-7351-RES-0402]
R2  10K  [SM-7351-RES-0402]
R4  1M  [SM-7351-RES-0402]
R5  0  [SM-7351-RES-0402]
R6  0  [SM-7351-RES-0402]
R7  0  [SM-7351-RES-0402]
R8  0  [SM-7351-RES-0402]
R9  10K  [SM-7351-RES-0402]
R10  0  [SM-7351-RES-0402]
R11  100  [SM-7351-RES-0402]
R12  100  [SM-7351-RES-0402]
R13  0  [SM-7351-RES-0402]
R14  0  [SM-7351-RES-0402]
R15  0  [SM-7351-RES-0402]
R16  0  [SM-7351-RES-0402]
R17  0  [SM-7351-RES-0402]
R18  10K  [SM-7351-RES-0402]
SW2  B3SL  [SW_B3SL-1022P]
SW3  SwitchTactileNO  [SW-B3U-1100P]
TP1  TP1mm  [tp_smd1mmcircle]
U2  SN74LVC1G07  [SC70-5-43M]
U47  TPD1E10B06  [tpd1e10b06-2l]
U48  TPD1E10B06  [tpd1e10b06-2l]
Y1  24MHz  [XTAL2X3-30M]
Y2  32.768KHz MC-306  [MC-306]
sheet Pg03: Processor Power
C9  0.01uF  [SM-7351-CAP-0402]
C10  10uF  [SM-7351-CAP-0805]
C11  0.01uF  [SM-7351-CAP-0402]
C12  0.01uF  [SM-7351-CAP-0402]
C13  0.01uF  [SM-7351-CAP-0402]
C14  0.01uF  [SM-7351-CAP-0402]
C15  0.01uF  [SM-7351-CAP-0402]
C16  10uF  [SM-7351-CAP-0805]
C17  0.01uF  [SM-7351-CAP-0402]
C18  0.01uF  [SM-7351-CAP-0402]
C19  10uF  [SM-7351-CAP-0805]
C20  0.01uF  [SM-7351-CAP-0402]
C21  10uF  [SM-7351-CAP-0805]
C22  0.01uF  [SM-7351-CAP-0402]
C23  0.01uF  [SM-7351-CAP-0402]
C24  0.01uF  [SM-7351-CAP-0402]
C25  10uF  [SM-7351-CAP-0805]
C26  0.01uF  [SM-7351-CAP-0402]
C27  0.01uF  [SM-7351-CAP-0402]
C28  10uF  [SM-7351-CAP-0805]
C29  0.01uF  [SM-7351-CAP-0402]
C30  0.01uF  [SM-7351-CAP-0402]
C31  0.01uF  [SM-7351-CAP-0402]
C32  0.01uF  [SM-7351-CAP-0402]
C33  0.01uF  [SM-7351-CAP-0402]
C34  0.01uF  [SM-7351-CAP-0402]
C35  0.01uF  [SM-7351-CAP-0402]
C36  0.01uF  [SM-7351-CAP-0402]
C37  0.01uF  [SM-7351-CAP-0402]
C38  0.01uF  [SM-7351-CAP-0402]
C39  0.01uF  [SM-7351-CAP-0402]
C40  0.01uF  [SM-7351-CAP-0402]
C41  10uF  [SM-7351-CAP-0805]
C42  0.01uF  [SM-7351-CAP-0402]
C43  10uF  [SM-7351-CAP-0805]
C44  0.01uF  [SM-7351-CAP-0402]
C45  0.01uF  [SM-7351-CAP-0402]
C49  10uF  [SM-7351-CAP-0805]
C50  0.01uF  [SM-7351-CAP-0402]
C51  0.01uF  [SM-7351-CAP-0402]
C52  0.01uF  [SM-7351-CAP-0402]
C53  0.01uF  [SM-7351-CAP-0402]
C54  0.01uF  [SM-7351-CAP-0402]
C55  0.01uF  [SM-7351-CAP-0402]
C56  0.01uF  [SM-7351-CAP-0402]
C57  1uF  [SM-7351-CAP-0402]
C58  1uF  [SM-7351-CAP-0402]
C59  1uF  [SM-7351-CAP-0402]
C60  1uF  [SM-7351-CAP-0402]
C63  10uF  [SM-7351-CAP-0805]
C64  0.01uF  [SM-7351-CAP-0402]
C65  0.01uF  [SM-7351-CAP-0402]
C66  0.01uF  [SM-7351-CAP-0402]
C67  0.01uF  [SM-7351-CAP-0402]
C68  0.01uF  [SM-7351-CAP-0402]
C69  0.01uF  [SM-7351-CAP-0402]
C199  0.01uF  [SM-7351-CAP-0402]
C314  0.01uF  [SM-7351-CAP-0402]
C400  0.1uF  [SM-7351-CAP-0402]
C401  0.1uF  [SM-7351-CAP-0402]
C402  0.1uF  [SM-7351-CAP-0402]
C413  10uF  [SM-7351-CAP-0805]
C414  0.01uF  [SM-7351-CAP-0402]
C415  0.01uF  [SM-7351-CAP-0402]
C416  10uF  [SM-7351-CAP-0603]
C417  0.01uF  [SM-7351-CAP-0402]
C418  0.01uF  [SM-7351-CAP-0402]
C419  0.01uF  [SM-7351-CAP-0402]
C420  0.01uF  [SM-7351-CAP-0402]
C421  0.01uF  [SM-7351-CAP-0402]
C422  0.01uF  [SM-7351-CAP-0402]
C423  10uF  [SM-7351-CAP-0603]
C424  0.01uF  [SM-7351-CAP-0402]
C431  0.01uF  [SM-7351-CAP-0402]
C432  2.2uF  [SM-7351-CAP-0805]
C458  0.01uF  [SM-7351-CAP-0402]
C459  0.01uF  [SM-7351-CAP-0402]
C462  0.01uF  [SM-7351-CAP-0402]
FB18  150OHM800mA  [sm-7351-ind-0805]
FB19  150OHM800mA  [sm-7351-ind-0805]
FB20  150OHM800mA  [sm-7351-ind-0805]
FB21  150OHM800mA  [sm-7351-ind-0805]
FB22  150OHM800mA  [sm-7351-ind-0805]
FB23  150OHM800mA  [sm-7351-ind-0805]
FB24  150OHM800mA  [sm-7351-ind-0805]
FB25  150OHM800mA  [sm-7351-ind-0805]
FB26  150OHM800mA  [sm-7351-ind-0805]
FB27  150OHM800mA  [sm-7351-ind-0805]
J30  HEADER 2  [header_2x1]
J31  HEADER 2  [header_2x1]
J32  HEADER 2  [header_2x1]
R20  0  [SM-7351-RES-0603]
R21  0  [SM-7351-RES-0603]
R22  0  [SM-7351-RES-0603]
R23  0.1ohm1% Sense  [SM_RES_0805_KELV]
R24  0.1ohm1% Sense  [SM_RES_0805_KELV]
R38  0.05ohm1% Sense  [SM_RES_LVK12]
R526  0.05ohm1% Sense  [SM_RES_LVK12]
R527  0.05ohm1% Sense  [SM_RES_LVK12]
R622  0  [SM-7351-RES-0402]
R623  0  [SM-7351-RES-0402]
R695  0  [SM-7351-RES-0402]
R701  0  [SM-7351-RES-0402]
sheet Pg04: Power Supply - PMIC
C72  0.1uF  [SM-7351-CAP-0402]
C73  0.1uF  [SM-7351-CAP-0402]
C74  10uF  [SM-7351-CAP-0805]
C75  1uF  [SM-7351-CAP-0603]
C76  100uF  [SM-7351-CAP-smdcan]
C77  100uF  [SM-7351-CAP-smdcan]
C78  4.7uF  [SM-7351-CAP-0603]
C79  4.7uF  [SM-7351-CAP-0603]
C80  22uF  [SM-7351-CAP-0603]
C81  4.7uF  [SM-7351-CAP-0603]
C82  1uF  [SM-7351-CAP-0402]
C83  22uF  [SM-7351-CAP-0603]
C84  4.7uF  [SM-7351-CAP-0603]
C85  10uF  [SM-7351-CAP-0805]
C86  4.7uF  [SM-7351-CAP-0603]
C87  10uF  [SM-7351-CAP-0805]
C88  4.7uF  [SM-7351-CAP-0603]
C89  10uF  [SM-7351-CAP-0805]
C90  10uF  [SM-7351-CAP-0805]
C91  10uF  [SM-7351-CAP-0805]
C92  4.7uF  [SM-7351-CAP-0603]
C93  10uF  [SM-7351-CAP-0805]
C406  22uF  [SM-7351-CAP-0805]
C409  220uF  [smd7343-122m]
D1  B520C-13-F  [B520C-13-F]
D2  SMCJ15CA  [SMCJ15CA]
D3  Green LED  [sm_led_0805]
D12  Green LED  [sm_led_0805]
F1  Fuse 4A  [smdfuseblk]
J3  HEADER 2  [header_2x1]
J4  Power Jack RAPC712  [RAPC712]
J9  HEADER 2  [header_2x1]
L1  10uH  [ind-mlz2012-57m]
L2  10uH  [ind-mlz2012-57m]
L3  1.5uH  [IND_SPM3012T]
L4  1.5uH  [IND_SPM3012T]
L5  1.5uH  [IND_SPM3012T]
L6  1.5uH  [IND_SPM3012T]
L12  DLW5BTN501SQ2L  [DLW5BTN501SQ2]
R48  150  [SM-7351-RES-0402]
R49  10K  [SM-7351-RES-0402]
R50  10K  [SM-7351-RES-0402]
R51  0  [SM-7351-RES-0402]
R52  10K  [SM-7351-RES-0402]
R53  0  [SM-7351-RES-0603]
R54  0  [SM-7351-RES-0402]
R55  10K  [SM-7351-RES-0402]
R56  0  [SM-7351-RES-0402]
R57  10K  [SM-7351-RES-0402]
R58  0  [SM-7351-RES-0402]
R59  0  [SM-7351-RES-0402]
R60  0  [SM-7351-RES-0402]
R61  0  [SM-7351-RES-0402]
R62  2.2K  [sm-7351-res-0402]
R63  33  [SM-7351-RES-0402]
R64  2.2K  [sm-7351-res-0402]
R67  0  [SM-7351-RES-0603]
R68  10K  [SM-7351-RES-0402]
R69  0  [SM-7351-RES-0402]
R70  12.1K, 1%  [SM-7351-RES-0402]
R72  1.4K  [SM-7351-RES-0402]
R392  0  [SM-7351-RES-0402]
R555  22K  [SM-7351-RES-0402]
R556  100K  [SM-7351-RES-0402]
SW14  SwitchTactileNOedge  [SW-B3U-3100P-B]
TP4  TP  [TH_TP_5002]
TP5  TP1mm  [tp_smd1mmcircle]
TP6  TP1mm  [tp_smd1mmcircle]
TP7  TP  [TH_TP_5002]
TP8  TP  [TH_TP_5002]
U1  AM437X_ZDN  [AM437X_ZDN]  (sections -1,-10,-11,-12,-13,-14,-15,-16,-17,-18,-19,-2,-20,-21,-3,-4,-5,-6,-7,-8,-9)
U3  TPS65218  [qfn6x6-48-39m]
U49  TPD1E10B06  [tpd1e10b06-2l]
sheet Pg05: QSPI NOR Flash Memory
C100  0.01uF  [SM-7351-CAP-0402]
R79  10K  [SM-7351-RES-0402]
R80  0  [SM-7351-RES-0402]
R81  0  [SM-7351-RES-0402]
R82  0  [SM-7351-RES-0402]
R83  0  [SM-7351-RES-0402]
R84  0  [SM-7351-RES-0402]
R85  0  [SM-7351-RES-0402]
U5  MX66L51235FMI  [soic_16pin_dw]
sheet Pg07: SDMMC0 Interface
C157  0.1uF  [SM-7351-CAP-0402]
C158  4.7uF  [SM-7351-CAP-0603]
J5  SCHA5B0200  [SD-MICRO-SCHA5B0300]
R127  100K  [SM-7351-RES-0402]
R128  10K  [SM-7351-RES-0402]
R129  10K  [SM-7351-RES-0402]
R130  10K  [SM-7351-RES-0402]
R131  10K  [SM-7351-RES-0402]
R132  0  [SM-7351-RES-0402]
R133  0  [SM-7351-RES-0402]
R134  0  [SM-7351-RES-0402]
R135  0  [SM-7351-RES-0402]
R136  0  [SM-7351-RES-0402]
R137  0  [SM-7351-RES-0402]
R138  470K  [SM-7351-RES-0402]
R139  0  [SM-7351-RES-0402]
U8  TPD1E10B06  [tpd1e10b06-2l]
U10  TPD6E001  [U_10_RSE]
sheet Pg11: LCD/Touchscreen
A1  NHD-4.3-480272EF-ATXL#-CTP  [DNP]
C46  10uF  [SM-7351-CAP-0805]
C216  4.7uF  [SM-7351-CAP-0603]
C221  4.7uF  [SM-7351-CAP-0805]
C463  0.01uF  [SM-7351-CAP-0402]
C467  0.01uF  [SM-7351-CAP-0402]
J1  54132-4097  [CNFPC1X40-0P5MM]
J2  0522070685  [CN52271-0679]
L8  4.7uH  [vlcf5020t]
Q4  BSS138  [SOT23-3]
R3  0  [SM-7351-RES-0402]
R231  0  [SM-7351-RES-0402]
R232  0  [SM-7351-RES-0402]
R233  10K  [SM-7351-RES-0402]
R234  10  [SM-7351-RES-0402]
R235  10, 1%  [sm-7351-res-0603]
R236  44.2K, 1%  [sm-7351-res-0603]
R237  0  [SM-7351-RES-0402]
R238  10K  [SM-7351-RES-0402]
R239  0  [SM-7351-RES-0402]
R240  0  [SM-7351-RES-0402]
R241  10K  [SM-7351-RES-0402]
U18  TPS61081DRC  [u_10_drc]
sheet Pg13: USB Port #0
C94  0.1uF  [SM-7351-CAP-0402]
C95  4.7uF  [SM-7351-CAP-0603]
C96  2.2uF  [SM-7351-CAP-0402]
C97  22uF  [SM-7351-CAP-0805]
C98  22uF  [SM-7351-CAP-0805]
C99  0.1uF  [SM-7351-CAP-0402]
C243  150uF  [SM-7351-CAP-2917]
C244  4.7uF  [SM-7351-CAP-0603]
C245  0.01uF  [SM-7351-CAP-0402]
C470  0.1uF  [SM-7351-CAP-0402]
FB12  150OHM800mA  [sm-7351-ind-0805]
J16  HEADER 2  [header_2x1]
J17  USB_MicroAB  [ZX62-AB-5PA]
L7  4.7uH  [smd_slf7055t]
L9  ACM2012  [ACM2012H]
Q9  BSS138  [SOT23-3]
R76  100K  [SM-7351-RES-0402]
R77  1.62M  [SM-7351-RES-0402]
R78  180K  [SM-7351-RES-0402]
R257  0  [SM-7351-RES-0402]
R259  0  [SM-7351-RES-0402]
R377  10K  [SM-7351-RES-0402]
R391  10K  [SM-7351-RES-0402]
R553  1K  [SM-7351-RES-0402]
R706  0  [SM-7351-RES-0402]
R743  10K  [SM-7351-RES-0402]
U4  TPS63010  [u_20_dsbga]
U26  TPD4S012  [U_6_DRY]
U34  TPS2051BD  [U_8_D]
sheet Pg14: USB Port #1
C252  150uF  [SM-7351-CAP-2917]
C253  4.7uF  [SM-7351-CAP-0603]
C254  0.01uF  [SM-7351-CAP-0402]
C469  0.1uF  [SM-7351-CAP-0402]
FB13  150OHM800mA  [sm-7351-ind-0805]
J19  USB A  [usb_std_a_th]
L11  ACM2012  [ACM2012H]
R265  10K  [SM-7351-RES-0402]
R266  0  [SM-7351-RES-0603]
R269  0  [SM-7351-RES-0402]
R271  10K  [SM-7351-RES-0402]
R552  1K  [SM-7351-RES-0402]
R741  0  [SM-7351-RES-0402]
U28  TPS2051BD  [U_8_D]
U29  TPD4S012  [U_6_DRY]
sheet Pg16: Wireless/Bluetooth WLink8
C255  0.01uF  [SM-7351-CAP-0402]
C256  0.01uF  [SM-7351-CAP-0402]
C261  15pF  [SM-7351-CAP-0402]
C262  2.2uF  [SM-7351-CAP-0805]
C263  1uF  [SM-7351-CAP-0402]
C318  0.01uF  [SM-7351-CAP-0402]
C319  0.01uF  [SM-7351-CAP-0402]
C320  0.01uF  [SM-7351-CAP-0402]
C321  0.01uF  [SM-7351-CAP-0402]
C322  0.01uF  [SM-7351-CAP-0402]
C323  0.01uF  [SM-7351-CAP-0402]
C324  0.01uF  [SM-7351-CAP-0402]
C325  0.01uF  [SM-7351-CAP-0402]
C326  0.01uF  [SM-7351-CAP-0402]
C327  0.01uF  [SM-7351-CAP-0402]
J20  MEC6_100pin  [MEC6-150-02-S-D-RA1]
R272  0  [SM-7351-RES-0402]
R274  10K  [SM-7351-RES-0402]
R275  10K  [SM-7351-RES-0402]
R276  10K  [SM-7351-RES-0402]
R277  10K  [SM-7351-RES-0402]
R278  10K  [SM-7351-RES-0402]
R279  10K  [SM-7351-RES-0402]
R280  0  [SM-7351-RES-0402]
R281  0  [SM-7351-RES-0402]
R282  0  [SM-7351-RES-0402]
R283  0  [SM-7351-RES-0402]
R284  0  [SM-7351-RES-0402]
R285  0  [SM-7351-RES-0402]
R286  0  [SM-7351-RES-0402]
R287  0  [SM-7351-RES-0402]
R288  0  [SM-7351-RES-0402]
R289  0  [SM-7351-RES-0402]
R290  0  [SM-7351-RES-0402]
R291  0  [SM-7351-RES-0402]
R292  0  [SM-7351-RES-0402]
R297  0  [SM-7351-RES-0402]
R301  0  [SM-7351-RES-0402]
R302  57.6K  [SM-7351-RES-0402]
R303  30.1K  [SM-7351-RES-0402]
TP20  TP1mm  [tp_smd1mmcircle]
U32  TPS79501  [sot223_6pin]
U51  SN74AVC2T244  [son2x1-8-16m]
U52  SN74AVC2T244  [son2x1-8-16m]
U53  SN74AVC2T244  [son2x1-8-16m]
U54  SN74AVC2T244  [son2x1-8-16m]
U55  SN74AVC2T244  [son2x1-8-16m]
sheet Pg17: Keypad/LED's
C264  1uF  [SM-7351-CAP-0402]
C265  1uF  [SM-7351-CAP-0402]
C267  1uF  [SM-7351-CAP-0402]
C268  1uF  [SM-7351-CAP-0402]
D7  Blue LED  [sm_led_0805]
D8  Blue LED  [sm_led_0805]
D9  Green LED  [sm_led_0805]
D10  Red LED  [sm_led_0805]
Q5  BSS138  [SOT23-3]
Q6  BSS138  [SOT23-3]
Q7  BSS138  [SOT23-3]
Q8  BSS138  [SOT23-3]
R304  0  [SM-7351-RES-0402]
R305  0  [SM-7351-RES-0402]
R306  2.2K  [sm-7351-res-0402]
R307  2.2K  [sm-7351-res-0402]
R309  2.2K  [sm-7351-res-0402]
R310  2.2K  [sm-7351-res-0402]
R312  150  [SM-7351-RES-0402]
R313  150  [SM-7351-RES-0402]
R314  150  [SM-7351-RES-0402]
R315  150  [SM-7351-RES-0402]
R316  0  [SM-7351-RES-0402]
R317  100K  [SM-7351-RES-0402]
R318  0  [SM-7351-RES-0402]
R319  0  [SM-7351-RES-0402]
R320  0  [SM-7351-RES-0402]
R321  100K  [SM-7351-RES-0402]
R322  100K  [SM-7351-RES-0402]
R323  100K  [SM-7351-RES-0402]
SW6  B3SL  [SW_B3SL-1022P]
SW7  B3SL  [SW_B3SL-1022P]
SW8  B3SL  [SW_B3SL-1022P]
SW9  B3SL  [SW_B3SL-1022P]
U44  TPD1E10B06  [tpd1e10b06-2l]
U45  TPD1E10B06  [tpd1e10b06-2l]

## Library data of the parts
C1 C2 = 1C_24pFCapacitor50V5%SMD0402
C3 C4 C6 C57-C60 C82 C263-C265 C267 C268 = 1C_1uFCapacitor10V10%0402
C5 C9 C11-C15 C17 C18 C20 C22-C24 C26 C27 C29-C40 C42 C44 C45 C50-C56 C64-C69 C100 C199 C245 C254-C256 C314 C318-C327 C414 C415 C417-C422 C424 C431 C458 C459 C462 C463 C467 = 1C_0.01uFCapacitor16V10%0402
C7 C8 C261 = 1C_15pFCapacitor50V10%smd0402
R1 R2 R9 R18 R49 R50 R52 R55 R57 R68 R79 R128-R131 R233 R238 R241 R265 R271 R274-R279 R377 R391 R743 = 1R_10KOhmResistor1_16W0402
R4 = 1MOhmResistor1_16W0402
R3 R5-R8 R10 R13-R17 R51 R54 R56 R58-R61 R69 R80-R85 R132-R137 R139 R231 R232 R237 R239 R240 R257 R259 R269 R272 R280-R292 R297 R301 R304 R305 R316 R318-R320 R392 R622 R623 R695 R701 R706 R741 = 1R_ZeroOhmResistor1_16W0402
R11 R12 = 1R_100ohm1_16W1%SMD0402
SW2 SW6-SW9 = 2W_Switch_Pushbuttonsmd
SW3 = 2W_SwitchTactileNO_wgnd_smd
TP1 TP5 TP6 TP20 = 2H_Testpoint_SMD1mmCircle
U2 = 1A_SN74LVC1G07
U8 U44 U45 U47-U49 = 1A_TPD1E10B06
Y1 = 1Y_Crystal24MHzSCM
Y2 = 1Y_Crystal_SMD32_768kHz
C10 C16 C19 C21 C25 C28 C41 C43 C46 C49 C63 C74 C85 C87 C89-C91 C93 C413 = 1C_10uFCapacitor16V10%0805
C72 C73 C99 C157 C400-C402 C469 C470 = 1C_0.1uFCapacitor16V10%0402
C416 C423 = 1C_10uFCapacitor6.3V20%0603
C262 C432 = 1C_2.2uF16V10%SMD0805
FB12 FB13 FB18-FB27 = 1L_FerBead_180ohm200mA
J3 J9 J16 J30-J32 = 2H_Header_2x1
R20-R22 R53 R67 R266 = 1R_ZeroOhmResistor1_16W0603
R23 R24 = 1R_0.1ohm0.33W1%Sense0805
R38 R526 R527 = 1R_0.05ohm0.5W1%Sense1206
C75 = 1C_1uFCapacitor50V10%0603
C76 C77 = 1C_100uFCapacitor16V20%ElecPoly
C78 C79 C81 C84 C86 C88 C92 C95 C158 C216 C244 C253 = 1C_4.7uFCapacitor16V10%0603
C80 C83 = 1C_22uFCapacitor6.3V20%0603
C97 C98 C406 = 1C_22uFCapacitor16V10%0805
C409 = 1C_220uFCapacitor16V10%Tantalum
D1 = 1E_Diode_5ARect
D2 = 1E_Diode_SMCJ15CA
D3 D9 D12 = 1F_LED_Green
F1 = 1P_Fuse_4A
J4 = 2J_Conn_PwrJack_RAPC712
L1 L2 = 1L_10uHInductor20%110mAsmd
L3-L6 = 1L_1.5uHInductor20%2.8Asmd
L12 = 1L_DLW5BTN501SQ2L
R48 R312-R315 = 1R_150ohm1_16W1%SMD0402
R62 R64 R306 R307 R309 R310 = 1R_2.2KOhmResistor1_16W0402
R63 = 1R_33ohmResistor1_16W5%0402
R70 = 1R_12.1KohmResistor1_16W1%0402
R72 = 1R_1.4KOhmResistor1_16W1%0402
R555 = 1R_22Kohm1_16W1%SMD0402
R76 R127 R317 R321-R323 R556 = 1R_100KOhmResistor1_16W0402
SW14 = 2W_SwitchTactileNOedge_wgnd_smd
TP4 TP7 TP8 = 2H_TestPointThroughHole
U1 = AM437x_ZDN_StarterKit: Color: Default; Cost100: 5.01; Cost10K: 3.95; DescriptiveText: Cortex A9 SOC AM437x; Location X-Coordinate: 0; Location Y-Coordinate: 0; Mfr: TI; MfrNum: AM437XZDN; PACKAGE: 1; Power Pins Visible: False; Primitive: DEFAULT; TIIntPartnumber: 1A0392; Vendor: TI
U3 = 1A_TPS65218
U5 = 1A_MX66L51235FMI
J5 = 2C_Conn_microSD_8
R138 = 470Kohm1_16W1%SMD0402
U10 = 1A_TPD6E001RSE
A1 = 4P_LCD_480x272_4.3inwCapTSC
C221 = 1C_4.7uFCapacitor50V20%0805
J1 = conn_40pin_0.5mm_FFC
J2 = 2C_Conn_FFC_0522070685
L8 = 1L_4.7uHInductor30%1.7Asmd
Q4-Q9 = 1Q_MOSFET_NChan_BSS138
R234 = 1R_10ohm1_16W5%smd0402
R235 = 1R_10OhmResistor1_10W0603
R236 = 1R_44.2KOhmResistor1_10W1%0603
U18 = 1A_TPS61081DRC
C94 = 1C_0.1uFCapacitor16V10%0402: Installed: DNI
C96 = 1C_2.2uFCapacitor6.3V20%X5R0402
C243 C252 = 1C_150uFCapacitor10V10%2917
J17 = 2C_MicroUSBAB
L7 = 1L_4.7uHInductor30%3.1Asmd
L9 L11 = 1M_ACM2012
R77 = 1R_1.62MOhmResistor1_16W0402
R78 = 1R_180KOhmResistor1_16W0402
R552 R553 = 1R_1KOhmResistor1_16W0402
U4 = 1A_TPS63010YFF
U26 U29 = 1A_TPD4S012
U28 U34 = 1A_TPS2051BD
J19 = 2C_Connector_USB_A
J20 = 2C_Conn_SamtecMEC6_150
R302 = 1R_57.6Kohm1_10W1%smd0402
R303 = 1R_30.1Kohm1_16W1%smd0402
U32 = 1A_TPS79501
U51-U55 = 1A_SN74AVC2T244
D7 D8 = 1F_LED_Blue
D10 = 1F_LED_Red

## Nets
DGND: C3.2 C4.2 C5.2 C6.2 C9.2 C10.2 C11.2 C12.2 C13.2 C14.2 C15.2 C16.2 C17.2 C18.2 C19.2 C20.2 C21.2 C22.2 C23.2 C24.2 C25.2 C26.2 C27.2 C28.2 C29.2 C30.2 C31.2 C32.2 C33.2 C34.2 C35.2 C36.2 C37.2 C38.2 C39.2 C40.2 C41.2 C42.2 C43.2 C44.2 C45.2 C46.2 C49.2 C50.2 C51.2 C52.2 C53.2 C56.2 C57.2 C58.2 C59.2 C60.2 C63.2 C64.2 C65.2 C66.2 C67.2 C68.2 C69.2 C72.2 C73.2 C74.2 C75.2 C76.2(NEG) C77.2(NEG) C78.2 C79.2 C80.2 C81.2 C82.2 C83.2 C84.2 C85.2 C86.2 C87.2 C88.2 C89.2 C90.2 C91.2 C92.2 C93.2 C94.2 C95.2 C96.2 C97.2 C98.2 C99.2 C100.2 C157.2 C158.2 C199.2 C216.2 C221.2 C243.2(NEG) C244.2 C245.2 C252.2(NEG) C253.2 C254.2 C255.2 C256.2 C262.2 C263.2 C264.2 C265.2 C267.2 C268.2 C314.2 C318.2 C319.2 C320.2 C321.2 C322.2 C323.2 C324.2 C325.2 C326.2 C327.2 C406.2 C409.2(NEG) C413.2 C414.2 C415.2 C416.2 C417.2 C418.2 C419.2 C420.2 C421.2 C422.2 C423.2 C424.2 C431.2 C432.2 C458.2 C459.2 C462.2 C463.2 C467.2 C469.2 C470.2 D2.2(ANODE) D3.1(Cathode) D12.1(Cathode) FB12.1 FB13.1 J1.3 J1.29 J1.36 J1.41 J1.42 J2.2 J3.2 J5.6(VSS) J5.9(GND) J5.11(GND3) J5.12(GND4) J5.13(GND5) J5.14(GND6) J5.15(GND7) J5.16(GND8) J9.2 J17.5(GND) J19.4(GND) J20.2 J20.3 J20.6 J20.9 J20.18 J20.19 J20.22 J20.35 J20.37 J20.39 J20.42 J20.47 J20.60 J20.63 J20.64 J20.77 J20.83 J20.87 J20.92 J20.95 J20.97 L12.3 Q4.S(SOURCE) Q5.S(SOURCE) Q6.S(SOURCE) Q7.S(SOURCE) Q8.S(SOURCE) Q9.S(SOURCE) R8.1(P1) R14.1(P1) R21.2(P2) R70.2 R78.1(P1) R127.1(P1) R235.1(P1) R236.1(P1) R238.1(P1) R271.2(P2) R303.1(P1) R306.1(P1) R307.1(P1) R309.1(P1) R310.1(P1) R317.1(P1) R321.1(P1) R322.1(P1) R323.1(P1) R377.2(P2) R392.1(P1) R556.1(P1) R623.1(P1) R701.1(P1) R706.1(P1) R741.1(P1) SW2.1 SW2.2 SW3.1(A1) SW3.3(A3) SW14.1(A1) SW14.3(A3) TP7.1 TP8.1 U1.A1(GND) U1.A25(GND) U1.AE1(GND) U1.AE25(GND) U1.H15(GND) U1.H18(GND) U1.J9(GND) U1.J12(GND) U1.J15(GND) U1.J17(GND) U1.K9(GND) U1.K11(GND) U1.K12(GND) U1.K14(GND) U1.K15(GND) U1.L8(GND) U1.L9(GND) U1.L11(GND) U1.L15(GND) U1.L17(GND) U1.L18(GND) U1.M10(GND) U1.M11(GND) U1.M13(GND) U1.M15(GND) U1.M16(GND) U1.N10(GND) U1.N11(GND) U1.N12(GND) U1.N13(GND) U1.N14(GND) U1.N15(GND) U1.P8(GND) U1.P9(GND) U1.P10(GND) U1.P11(GND) U1.P12(GND) U1.P13(GND) U1.P14(GND) U1.P15(GND) U1.R12(GND) U1.R15(GND) U1.R17(GND) U1.R18(GND) U1.T12(GND) U1.T15(GND) U1.T17(GND) U1.U8(GND) U1.U9(GND) U1.U10(GND) U1.U11(GND) U1.U12(GND) U1.U13(GND) U1.U14(GND) U1.U16(GND) U1.U17(GND) U1.U18(GND) U1.U19(GND) U1.V9(GND) U1.V10(GND) U1.V11(GND) U1.V12(GND) U1.V13(GND) U1.V14(GND) U1.V18(GND) U1.W23(VSSA_USB) U2.3(GND) U3.TPAD(GNDP) U4.B4(SYNC) U4.C1(PGND) U4.C2(PGND) U4.C3(GND) U4.D3(GND) U4.E4(GND) U5.10(GND) U8.2 U10.5(GND) U18.4(GND) U18.8(PGND) U18.PAD(TPAD) U26.4(GND) U28.1(GND) U29.4(GND) U32.3(GND) U32.6(GND) U34.1(GND) U44.2 U45.2 U47.2 U48.2 U49.2 U51.4(~{OE}) U51.5(GND) U52.4(~{OE}) U52.5(GND) U53.3(A2) U53.4(~{OE}) U53.5(GND) U54.4(~{OE}) U54.5(GND) U55.4(~{OE}) U55.5(GND) ; also on sheet 1 3 4 5 6 7 8
GND_OSC0: C1.2 C2.2 R8.2(P2) U1.B24(VSS_OSC)
GND_OSC1: C7.2 C8.2 R14.2(P2) U1.AD4(VSS_RTC)
GND_PWRJCK: J4.2 J4.3 L12.4
GNDA_ADC: C54.2 C55.2 R623.2(P2) U1.AC15(VSSA_ADC) ; also on sheet 7
GNDUSB0: FB12.2 J17.S1 J17.S2 J17.S3 J17.S4
GNDUSB1: FB13.2 J19.S1 J19.S2
V1_0BAT: C80.1 L1.2 R22.2(P2) U3.21(FB5)
V1_8BAT: C83.1 L2.2 R695.1(P1) U3.22(FB6)
V1_8D: C255.1 C318.1 C320.1 C322.1 C324.1 C326.1 J20.8 J20.62 R23.1(I1) R53.1(P1) R274.2(P2) R275.2(P2) R276.2(P2) R277.2(P2) R278.2(P2) R279.2(P2) R301.2(P2) U51.8(VCCB) U52.1(VCCA) U53.1(VCCA) U54.8(VCCB) U55.1(VCCA) ; also on sheet 3 4
V1_8D_AM437X: C49.1 C50.1 C51.1 C52.1 C53.1 C199.1 C413.1 C414.1 C415.1 C421.1 C431.1 C458.1 C459.1 FB18.1 FB19.1 FB20.1 FB21.1 FB22.1 FB23.2 FB24.2 FB25.1 FB26.1 FB27.2 R23.2(I2) U1.AD8(VDDS_TPM) U1.C23(VDDS_OSC) U1.F20(VDDS) U1.G6(VDDS) U1.H12(VDDS) U1.P19(VDDS) U1.U21(VDDA1P8V_USB1) U1.V16(VDDSHV2) U1.V17(VDDSHV2) U1.W15(VDDS) U1.W16(VDDSHV2) U1.Y19(VDDS)
V3_3D: C46.1 C100.1 C157.1 C158.1 C319.1 C321.1 C323.1 C325.1 C327.1 C463.1 C467.1 J1.4 J2.1 J5.4(VDD) R1.2(P2) R2.2(P2) R9.2(P2) R24.1(I1) R52.2(P2) R57.2(P2) R62.2(P2) R63.2 R64.2(P2) R67.1(P1) R76.2(P2) R79.2(P2) R128.2(P2) R129.2(P2) R130.2(P2) R131.2(P2) R138.2(P2) R231.2(P2) R233.2(P2) R238.2(P2) R241.2(P2) R265.1(P1) R391.1(P1) R743.2(P2) U5.2(VCC) U10.10(VCC) U51.1(VCCA) U52.8(VCCB) U53.8(VCCB) U54.1(VCCA) U55.8(VCCB) ; also on sheet 1 3 4 5 7 8
V3_3D_AM437X: C9.1 C10.1 C11.1 C12.1 C13.1 C14.1 C15.1 C16.1 C17.1 C18.1 C19.1 C20.1 C25.1 C37.1 C38.1 C39.1 C40.1 C41.1 C42.1 C43.1 C44.1 C45.1 C462.1 R24.2(I2) R622.2(P2) U1.F16(VDDSHV7) U1.F22(VDDSHV5) U1.G10(VDDSHV10) U1.G11(VDDSHV9) U1.G13(VDDSHV8) U1.G14(VDDSHV8) U1.G16(VDDSHV6) U1.G17(VDDSHV6) U1.H8(VDDSHV11) U1.H9(VDDSHV11) U1.H10(VDDSHV10) U1.H11(VDDSHV9) U1.H17(VDDSHV6) U1.J7(VDDSHV1) U1.J8(VDDSHV1) U1.J18(VDDSHV3) U1.K17(VDDSHV3) U1.K18(VDDSHV3) U1.N18(VDDSHV3) U1.N19(VDDSHV3) U1.P18(VDDSHV3) U1.W18(VDDSHV3)
V5_0D: C96.1 C97.1 C98.1 R77.2(P2) U4.E1(VOUT) U4.E2(VOUT) U28.2(IN) U28.3(IN) U34.2(IN) U34.3(IN)
V5_0D_EN: R76.1(P1) U4.A4(EN)
VBAT: C72.1 C73.1 C74.1 C75.1 C76.1(POS) C77.1(POS) C79.1 C81.1 C84.1 C86.1 C88.1 C92.1 C94.1 C95.1 C216.1 C263.1 C409.1(POS) D2.1(CATHODE) F1.2 R48.2(P2) R49.2(P2) R50.2(P2) R232.2(P2) R312.2(P2) R313.2(P2) R314.2(P2) R315.2(P2) R555.2(P2) TP4.1 U3.1(IN_DCDC1) U3.5(IN_LDO1) U3.12(IN_DCDC4) U3.27(IN_BU) U3.36(IN_BIAS) U3.37(IN_DCDC3) U3.43(IN_DCDC2) U4.A1(VIN) U4.A2(VIN) U18.2(VIN) U32.2(IN) ; also on sheet 3
VBUS0_OTG_CAP: C243.1(POS) J16.2
VBUS1_OTG_CAP: C252.1(POS) R266.2(P2)
VDD_CORE: C21.1 C22.1 C23.1 C24.1 C26.1 C27.1 C34.1 C35.1 C36.1 R526.2(I2) U1.AD9(VDD_TPM) U1.J10(VDD_CORE) U1.J11(VDD_CORE) U1.L12(VDD_CORE) U1.L14(VDD_CORE) U1.M9(VDD_CORE) U1.M12(VDD_CORE) U1.M14(VDD_CORE) U1.N9(VDD_CORE) U1.N16(VDD_CORE) U1.N17(VDD_CORE) U1.P16(VDD_CORE) U1.P17(VDD_CORE) U1.R9(VDD_CORE) U1.R11(VDD_CORE) U1.R14(VDD_CORE) U1.T9(VDD_CORE) U1.T11(VDD_CORE) U1.T14(VDD_CORE) U1.T18(VDD_CORE) U1.T19(VDD_CORE) U1.U15(VDD_CORE) U1.V15(VDD_CORE) U1.W12(VDD_CORE) U1.W13(VDD_CORE)
VDD_MPU: C28.1 C29.1 C30.1 C31.1 C32.1 C33.1 R527.2(I2) U1.H13(VDD_MPU) U1.H14(VDD_MPU) U1.H16(VDD_MPU) U1.J13(VDD_MPU) U1.J14(VDD_MPU) U1.J16(VDD_MPU) U1.K19(VDD_MPU) U1.K20(VDD_MPU) U1.L19(VDD_MPU) U1.L20(VDD_MPU) U1.M17(VDD_MPU) U1.M18(VDD_MPU)
VDDA1_8_USB0: C419.1 C432.1 FB18.2 U1.W21(VDDA1P8V_USB0)
VDDA1P8_PMLDO: R20.1(P1) U1.D6(VDDA1P8_PMLDO)
VDDA3_3_USB: C420.1 R622.1(P1) U1.U20(VDDA_3P3V_USB1) U1.W20(VDDA_3P3V_USB0)
VDDA3P3_PMLDO: R21.1(P1) U1.F8(VDDA3P3_PMLDO)
VDDA_ADC: C54.1 FB24.1 U1.AB12(VDDA_TS_ADC) ; also on sheet 7
VDDA_MC_ADC: C55.1 FB23.1 U1.Y16(VDDA_MC_ADC)
VDDS_CTM: FB27.1 U1.AD12(VDDS_CTM)
VDDS_PLL_CORE_LCD: C418.1 FB21.2 U1.N21(VDDS_PLL_CORE_LCD)
VDDS_PLL_DDR: C417.1 FB20.2 U1.G5(VDDS_PLL_DDR)
VDDS_PLL_MPU: C422.1 FB22.2 U1.E17(VDDS_PLL_MPU)
VDDS_RTC: C56.1 R18.1(P1) R55.2(P2) R695.2(P2) U1.AD5(VDDS_RTC)
VDDS_SRAM_CORE_BG: C416.1 FB25.2 U1.F13(VDDS_SRAM_CORE_BG)
VDDS_SRAM_MPU_BB: C423.1 FB26.2 U1.F14(VDDS_SRAM_MPU_BB)
VINT_LDO: C5.1 C406.1 U2.5(VCC) U3.35(INT_LDO)
ACCEL_INT1: U1.C8(GPMC_AD6) ; also on sheet 7
ACCEL_INT2: U1.A12(GPMC_CLK/MMC2_CLK) ; also on sheet 7
AM437X_COM_BTRST: R297.2(P2) U1.AC24(CAM1_DATA9/GPIO)
AM437X_COM_PPSOUT: R288.1(P1) U1.AD25(CAM1_HD/GPIO)
AM437X_COM_TIMESTAMP: R287.1(P1) U1.AC23(CAM1_VD/GPIO)
AM437X_COM_WLANIRQ: R286.1(P1) U1.AB25(CAM1_WEN/GPIO)
AM437X_COM_WLRST: R272.1(P1) U1.AD24(CAM1_DATA8/GPIO)
AM437X_I2C0_SCL: R60.2(P2) R64.1(P1) U1.Y22(I2C_SCL0) ; also on sheet 7
AM437X_I2C0_SDA: R61.2(P2) R62.1(P1) U1.AB24(I2C_SDA0) ; also on sheet 7
AM437X_LCD_AC_BIAS_EN: J1.34 U1.A24(DSS_AC_BIAS_EN) ; also on sheet 7
AM437X_LCD_DATA0: J1.21 U1.B22(DSS_DATA0) ; also on sheet 7
AM437X_LCD_DATA1: J1.22 U1.A21(DSS_DATA1) ; also on sheet 7
AM437X_LCD_DATA2: J1.23 U1.B21(DSS_DATA2) ; also on sheet 7
AM437X_LCD_DATA3: J1.24 U1.C21(DSS_DATA3) ; also on sheet 7
AM437X_LCD_DATA4: J1.25 U1.A20(DSS_DATA4) ; also on sheet 7
AM437X_LCD_DATA5: J1.26 U1.B20(DSS_DATA5) ; also on sheet 7
AM437X_LCD_DATA6: J1.27 U1.C20(DSS_DATA6) ; also on sheet 7
AM437X_LCD_DATA7: J1.28 U1.E19(DSS_DATA7) ; also on sheet 7
AM437X_LCD_DATA8: J1.13 U1.A19(DSS_DATA8) ; also on sheet 7
AM437X_LCD_DATA9: J1.14 U1.B19(DSS_DATA9) ; also on sheet 7
AM437X_LCD_DATA10: J1.15 U1.A18(DSS_DATA10) ; also on sheet 7
AM437X_LCD_DATA11: J1.16 U1.B18(DSS_DATA11) ; also on sheet 7
AM437X_LCD_DATA12: J1.17 U1.C19(DSS_DATA12) ; also on sheet 7
AM437X_LCD_DATA13: J1.18 U1.D19(DSS_DATA13) ; also on sheet 7
AM437X_LCD_DATA14: J1.19 U1.C17(DSS_DATA14) ; also on sheet 7
AM437X_LCD_DATA15: J1.20 U1.D17(DSS_DATA15) ; also on sheet 7
AM437X_LCD_DATA16: J1.5 U1.A11(GPMC_AD15/DSS_DATA16)
AM437X_LCD_DATA17: J1.6 U1.B11(GPMC_AD14/DSS_DATA17)
AM437X_LCD_DATA18: J1.7 U1.C11(GPMC_AD13/DSS_DATA18)
AM437X_LCD_DATA19: J1.8 U1.E11(GPMC_AD12/DSS_DATA19)
AM437X_LCD_DATA20: J1.9 U1.D11(GPMC_AD11/DSS_DATA20)
AM437X_LCD_DATA21: J1.10 U1.F11(GPMC_AD10/DSS_DATA21)
AM437X_LCD_DATA22: J1.11 U1.A10(GPMC_AD9/DSS_DATA22)
AM437X_LCD_DATA23: J1.12 U1.B10(GPMC_AD8/DSS_DATA23)
AM437X_LCD_DISEN: J1.31 U1.B8(GPMC_AD7)
AM437X_LCD_HSYNC: J1.32 U1.A23(DSS_HSYNC) ; also on sheet 7
AM437X_LCD_PCLK: R3.2(P2) U1.A22(DSS_PCLK)
AM437X_LCD_VSYNC: J1.33 U1.B23(DSS_VSYNC) ; also on sheet 7
AM437X_MMC0_CLK: R135.2(P2) U1.D1(MMC0_CLK)
AM437X_MMC0_CMD: R134.2(P2) U1.D2(MMC0_CMD)
AM437X_MMC0_DAT0: R136.2(P2) U1.C1(MMC0_DAT0)
AM437X_MMC0_DAT1: R137.2(P2) U1.C2(MMC0_DAT1)
AM437X_MMC0_DAT2: R132.2(P2) U1.B2(MMC0_DAT2)
AM437X_MMC0_DAT3: R133.2(P2) U1.B1(MMC0_DAT3)
AM437X_MMC0_SDCD: R139.2(P2) U1.R25(SPI0_CS1/MMC0_SDCD)
AM437X_NMIn: R10.1(P1) R51.1(P1) U1.G25(NMIn)
AM437X_OSC0_IN: C2.1 R4.2(P2) U1.C25(OSC0_IN) Y1.3
AM437X_OSC0_OUT: R5.1(P1) U1.B25(OSC0_OUT)
AM437X_PORZn: R6.1(P1) U1.Y23(PORZn)
AM437X_QSPI_CLK: R80.2(P2) U1.B12(GPMC_CSN3/QSPI_CLK)
AM437X_QSPI_CSn: R85.2(P2) U1.A8(GPMC_CS0n/QSPI_CSn)
AM437X_QSPI_D0: R81.2(P2) U1.A9(GPMC_ADVN_ALE/QSPI_D0)
AM437X_QSPI_D1: R82.2(P2) U1.E10(GPMC_OEN_REN/QSPI_D1)
AM437X_QSPI_D2: R83.2(P2) U1.D10(GPMC_WEN/QSPI_D2)
AM437X_QSPI_D3: R84.2(P2) U1.C10(GPMC_BE0N_CLE/QSPI_D3)
AM437X_USB0_DRVVBUS: R259.2(P2) U1.G21(USB0_DRVVBUS)
AM437X_USB0_ID: R257.2(P2) U1.U24(USB0_ID)
AM437X_USB0_VBUS: C470.1 R553.2(P2) U1.U23(USB0_VBUS)
AM437X_USB1_DM: L11.2 U1.V25(USB1_DM)
AM437X_USB1_DP: L11.1 U1.V24(USB1_DP)
AM437X_USB1_DRVVBUS: R269.2(P2) U1.F25(USB1_DRVVBUS)
AM437X_USB1_VBUS: C469.1 R552.2(P2) U1.T25(USB1_VBUS)
AM437X_VDD_DDR: C63.1 C64.1 C65.1 C66.1 C67.1 C68.1 C69.1 C314.1 R38.2(I2) U1.K7(VDD_DDR) U1.K8(VDD_DDR) U1.M7(VDD_DDR) U1.M8(VDD_DDR) U1.N7(VDD_DDR) U1.N8(VDD_DDR) U1.R6(VDD_DDR) U1.R7(VDD_DDR) U1.R8(VDD_DDR) U1.T7(VDD_DDR) U1.T8(VDD_DDR) U1.V7(VDD_DDR) U1.V8(VDD_DDR)
BKLT_EN: Q4.G(GATE) R233.1(P1) R237.1(P1)
BKLT_L: L8.1 U18.1(L)
BKLT_SW: L8.2 U18.10(SW)
CAP_VBB_MPU: C57.1 U1.F19(CAP_VBB_MPU)
CAP_VDD_SRAM_CORE: C59.1 U1.E13(CAP_VDD_SRAM_CORE)
CAP_VDD_SRAM_MPU: C58.1 U1.E14(CAP_VDD_SRAM_MPU)
COM_AUD_CLK: J20.52 R289.2(P2)
COM_AUD_FSYNC: J20.54 R290.2(P2)
COM_AUD_IN: J20.56 R291.2(P2)
COM_AUD_OUT: J20.58 R292.2(P2)
COM_BTRST: J20.89 R297.1(P1)
COM_BTUARTCTS: J20.70 U54.6(B2)
COM_BTUARTDEBUG: J20.76 TP20.1
COM_BTUARTRTS: J20.72 U55.3(A2)
COM_BTUARTRX: J20.68 U54.7(B1)
COM_BTUARTTX: J20.66 U55.2(A1)
COM_GNSS_PPS_OUT: J20.50 R288.2(P2)
COM_GNSS_TIME_STAMP: J20.48 R287.2(P2)
COM_SDIO_CLK: J20.20 R279.1(P1) R280.2(P2)
COM_SDIO_CMD: J20.24 R278.1(P1) R281.2(P2)
COM_SDIO_D0: J20.26 R274.1(P1) R282.2(P2)
COM_SDIO_D1: J20.28 R277.1(P1) R283.2(P2)
COM_SDIO_D2: J20.30 R276.1(P1) R284.2(P2)
COM_SDIO_D3: J20.32 R275.1(P1) R285.2(P2)
COM_SLOW_CLK: J20.1 U51.6(B2)
COM_WL_IRQ: J20.34 R286.2(P2)
COM_WL_RST: J20.4 R272.2(P2)
ETH1_INTn: U1.B7(GPMC_AD4/GPIO) ; also on sheet 8
ETH2_INTn: U1.A7(GPMC_AD5/GPIO) ; also on sheet 1
GP_I2C_SCL: J2.3 ; also on sheet 3 4 7
GP_I2C_SDA: J2.4 ; also on sheet 3 4 7
GPIO0: U1.L24(MCASP0_AHCLKX/GPIO) ; also on sheet 7
GPIO1: U1.L23(MCASP0_ACLKR/GPIO) ; also on sheet 7
GPIO2: U1.K23(MCASP0_FSR/GPIO) ; also on sheet 7
GPIO3: U1.M25(MCASP0_AXR1/GPIO) ; also on sheet 7
GPIO4: U1.P23(SPI0_SCLK/GPIO) ; also on sheet 7
GPIO5: U1.B5(GPMC_AD0/MMC1_DAT0) ; also on sheet 7
GPIO6: U1.A5(GPMC_AD1/MMC1_DAT1) ; also on sheet 7
KEYPAD_PWRA: R304.1(P1) SW6.1 SW6.2 SW7.1 SW7.2
KEYPAD_PWRB: R305.1(P1) SW8.1 SW8.2 SW9.1 SW9.2
KEYPAD_SCN0: C264.1 C267.1 R306.2(P2) R309.2(P2) SW6.3 SW6.4 SW8.3 SW8.4 U1.R24(PLAT_STST1/GPIO) U44.1
KEYPAD_SCN1: C265.1 C268.1 R307.2(P2) R310.2(P2) SW7.3 SW7.4 SW9.3 SW9.4 U1.P24(PLAT_STST2/GPIO) U45.1
LCD_BACKLIGHT: R237.2(P2) U1.G24(ECAP0_IN_PWM0_OUT)
LCD_PCLK: J1.30 R3.1(P1)
MMC2_CLK: R280.1(P1) U1.AD21(CAM1_DATA2/MMC2_CLK)
MMC2_CMD: R281.1(P1) U1.AE22(CAM1_DATA3/MMC2_CMD)
MMC2_DAT0: R282.1(P1) U1.AD22(CAM1_DATA4/MMC2_DAT0)
MMC2_DAT1: R283.1(P1) U1.AE23(CAM1_DATA5/MMC2_DAT1)
MMC2_DAT2: R284.1(P1) U1.AD23(CAM1_DATA6/MMC2_DAT2)
MMC2_DAT3: R285.1(P1) U1.AE24(CAM1_DATA7/MMC2_DAT3)
MMC_CD: J5.10(CD) R138.1(P1) R139.1(P1) U8.1
MMC_CLK: J5.5(CLOCK) R135.1(P1) U10.1(IO1)
MMC_CMD: J5.3(CMD) R128.1(P1) R134.1(P1) U10.7(IO5)
MMC_D0: J5.7(DAT0) R129.1(P1) R136.1(P1) U10.2(IO2)
MMC_D1: J5.8(DAT1) R130.1(P1) R137.1(P1) U10.3(IO3)
MMC_D2: J5.1(DAT2) R131.1(P1) R132.1(P1) U10.6(IO4)
MMC_D3: J5.2(CD/DAT3) R127.2(P2) R133.1(P1) U10.8(IO6)
OSC0_OUT: C1.1 R4.1(P1) R5.2(P2) Y1.1
PB_INTERRUPT: C4.1 R9.1(P1) R10.2(P2) SW2.3 SW2.4 U47.1
PMIC_I2C_SCL: R60.1(P1) U3.3(SCL)
PMIC_I2C_SDA: R61.1(P1) U3.2(SDA)
PMIC_IN_nCC: R59.2(P2) U3.18(IN_nCC)
PMIC_INTn: R51.2(P2) R52.1(P1) U3.45(INTn)
PMIC_L5: L1.1 U3.20(L5)
PMIC_L6: L2.1 U3.23(L6)
PMIC_LDO1: C85.1 R53.2(P2) U3.4(LDO1)
PMIC_PFI: R555.1(P1) R556.2(P2) U3.16(PFI)
PMIC_PGOOD: R56.2(P2) R57.1(P1) U3.8(PGOOD)
PMIC_PGOODBU: R58.2(P2) U3.19(PGOOD_BU)
PMIC_PWR_EN: R17.1(P1) U3.46(PWR_EN)
PMIC_SYS_BU: C82.1 U3.24(SYS_BU)
PMIC_WAKEUPn: R54.2(P2) R55.1(P1) U3.40(WAKEUPn)
PMU_PORZn: R15.1(P1) R58.1(P1)
PORZn: C3.1 R2.1(P1) R6.2(P2) R56.1(P1) U2.2(A)
SPIMEM_CLK: R80.1(P1) U5.16(SCLK)
SPIMEM_CS: R85.1(P1) U5.7(~{CS})
SPIMEM_D0: R81.1(P1) U5.15(SI/SIO0)
SPIMEM_D1: R82.1(P1) U5.8(SO/SIO1)
SPIMEM_D2: R79.1(P1) R83.1(P1) U5.9(~{WP}/SIO2)
SPIMEM_D3: R84.1(P1) U5.1(DNU/SIO3)
STATUS_LED0: R316.2(P2) U1.H24(UART3_TXD/GPIO)
STATUS_LED1: R318.2(P2) U1.H25(UART3_RXD/GPIO)
STATUS_LED2: R319.2(P2) U1.K24(UART3_RTSn/GPIO)
STATUS_LED3: R320.2(P2) U1.H22(UART3_CTSn/GPIO)
SYS_RESETn: R12.1(P1) ; also on sheet 1 4 5 8
SYS_WARMRESETn: C6.1 R1.1(P1) R7.2(P2) R11.1(P1) R12.2(P2) U2.4(Y)
TOUCH_INT: R239.2(P2) U1.B3(GPMC_WPn/GPIO)
TOUCH_WAKE: R240.2(P2) U1.A3(GPMC_BE1n/GPIO)
USB0_CONN_DM: J17.2(DM) L9.3 U26.2(D-)
USB0_CONN_DP: J17.3(DP) L9.4 U26.1(D+)
USB0_DM: L9.2 U1.W24(USB0_DM)
USB0_DP: L9.1 U1.W25(USB0_DP)
USB0_ID: J17.4(ID) Q9.G(GATE) R257.1(P1) R706.2(P2) U26.3(ID)
USB0_OVRCURn: R391.2(P2) U1.B9(GPMC_CSN1/GPIO) U34.5(~{OC})
USB0_VBUS_DET: Q9.D(DRAIN) R743.1(P1) U1.A2(GPMC_WAIT0)
USB0_VBUS_EN: R259.1(P1) R377.1(P1) U34.4(EN)
USB1_CONN_DM: J19.2(DM) L11.3 U29.2(D-)
USB1_CONN_DP: J19.3(DP) L11.4 U29.1(D+)
USB1_OVRCURn: R265.2(P2) U1.F10(GPMC_CSN2/GPIO) U28.5(~{OC})
USB1_VBUS_EN: R269.1(P1) R271.1(P1) U28.4(EN)
USB5V_FB: R77.1(P1) R78.2(P2) U4.E3(FB)
VCOM_BAT: C256.1 C261.1 C262.1 J20.5 J20.7 R302.2 U32.4(OUT)
VCOM_BATEN: R301.1(P1) U32.1(EN)
VCOM_BATFB: C261.2 R302.1 R303.2(P2) U32.5(FB)
VDCDC1: C87.1 L3.2 R526.1(I1) U3.47(FB1)
VDCDC2: C89.1 L4.2 R527.1(I1) U3.41(FB2)
VDCDC3: C90.1 L5.2 R68.2(P2) U3.31(IN_LS1) U3.39(FB3) ; also on sheet 6
VDCDC4: C91.1 R67.2(P2) U3.15(DCDC4)
VLED+: C221.1 J1.2 U18.9(OUT)
VLED-: J1.1 R235.2(P2) U18.5(FB)
VLS1: R38.1(I1) R69.1(P1)
VPMIC_LS1: C93.1 R69.2(P2) U3.30(LS1)
VPP: U1.P21(VPP)
VPWRIN_JCK: J4.1 L12.1
VPWRIN_PREFUSE: D1.1(CATHODE) F1.1
VUSB_VBUS0: C244.1 C245.1 J16.1 J17.1(VBUS) R553.1(P1) U26.6(VBUS) U34.6(OUT) U34.7(OUT) U34.8(OUT)
VUSB_VBUS1: C253.1 C254.1 J19.1(VBUS) R266.1(P1) R552.1(P1) U28.6(OUT) U28.7(OUT) U28.8(OUT) U29.6(VBUS)
WAKEUP0: R16.1(P1) R54.1(P1)
N13794415: R304.2(P2) U1.E24(PLAT_MTST5/GPIO)
N14122798: Q5.G(GATE) R316.1(P1) R317.2(P2)
N14122802: Q6.G(GATE) R318.1(P1) R321.2(P2)
N14122806: Q7.G(GATE) R319.1(P1) R322.2(P2)
N14122814: Q8.G(GATE) R320.1(P1) R323.2(P2)
N14123228: D7.1(Cathode) Q5.D(DRAIN)
N14123236: D7.2(Anode) R312.1(P1)
N14123256: D8.1(Cathode) Q6.D(DRAIN)
N14123268: D8.2(Anode) R313.1(P1)
N14123284: D9.2(Anode) R314.1(P1)
N14123288: D9.1(Cathode) Q7.D(DRAIN)
N14123296: D10.1(Cathode) Q8.D(DRAIN)
N14123312: D10.2(Anode) R315.1(P1)
N14719514: D3.2(Anode) R48.1(P1)
N15665994: R231.1(P1) U18.6(EN)
N15666000: R234.2(P2) R236.2(P2) U18.3(SS)
N15666010: Q4.D(DRAIN) R234.1(P1)
N15666038: R232.1(P1) U18.7(FSW)
N16762168: U1.N24(MCASP0_ACLKX) U52.7(B1)
N16762172: U1.H23(MCASP0_AXR0) U51.2(A1)
N16762176: U1.M24(MCASP0_AHCLKR/MCASP0_AXR2) U53.7(B1)
N16762212: U1.L22(UART1_RTSN) U54.3(A2)
N16763034: U1.N22(MCASP0_FSX) U52.6(B2)
N16763102: U1.L21(UART1_TXD) U54.2(A1)
N16763122: U1.K21(UART1_RXD) U55.7(B1)
N16763154: U1.K22(UART1_CTSN) U55.6(B2)
N16763684: R289.1(P1) U52.2(A1)
N16763692: R290.1(P1) U52.3(A2)
N16763708: R291.1(P1) U51.7(B1)
N16763720: R292.1(P1) U53.2(A1)
N16763914: U1.C24(XDMA_EVENT_INTR1/CLKOUT2) U51.3(A2)
N16767913: R305.2(P2) U1.P25(PLAT_STST0/GPIO)
N16863605: R7.1(P1) U1.G22(RESETIN_OUTn)
N16864609: R11.2(P2) SW3.2(A2) U48.1
N16865138: R18.2(P2) U1.AE2(RTC_KALDO_ENn)
N16865144: R17.2(P2) U1.AD6(RTC_PMIC_EN)
N16865169: R16.2(P2) U1.AE3(RTC_WAKEUP)
N16865200: R15.2(P2) U1.AE6(RTC_PORZ)
N16865253: R13.1(P1) U1.AE4(OSC1_OUT)
N16865255: C8.1 R13.2(P2) Y2.4
N16865261: C7.1 U1.AE5(OSC1_IN) Y2.1
N16975036: J9.1 R50.1(P1) SW14.2(A2) U3.44(PB) U49.1
N16975062: R49.1(P1) R392.2(P2) U3.9(AC_DET)
N16975327: C78.1 R72.2 U3.25(CC)
N16975333: J3.1 R72.1
N16975428: D12.2(Anode) R63.1
N16975488: TP5.1 U3.11(GPIO1)
N16975490: R68.1(P1) TP6.1 U3.34(GPO2)
N16975537: R70.1 U3.17(DC34_SEL)
N16975733: L6.1 U3.13(L4A)
N16975735: L5.1 U3.38(L3)
N16975743: L4.1 U3.42(L2)
N16975751: L3.1 U3.48(L1)
N16976027: L6.2 U3.14(L4B)
N16988129: C424.1 FB19.2 U1.E23(VDDS_CLKOUT)
N16988368: C60.1 R22.1(P1) U1.AD3(CAP_VDD_RTC)
N16988679: R701.2(P2) U1.AA23(TEST_EN)
N17083351: J2.5 R239.1(P1)
N17083353: J2.6 R240.1(P1) R241.1(P1)
N17113054: C400.1 J30.1 R526.3(SENS1)
N17113066: C400.2 J30.2 R526.4(SENS2)
N17113108: C401.1 J31.1 R527.3(SENS1)
N17113124: C401.2 J31.2 R527.4(SENS2)
N17113238: C402.1 J32.1 R38.3(SENS1)
N17113254: C402.2 J32.2 R38.4(SENS2)
N17185986: L7.1 U4.B1(L1) U4.B2(L1)
N17185996: L7.2 U4.D1(L2) U4.D2(L2)
N17186006: C99.1 U4.A3(VINA) U4.B3(VINA1) U4.C4(~{PS}) U4.D4(VSEL)
N17186974: D1.2(ANODE) L12.2
N17359788: R741.2(P2) U1.U25(USB1_ID)
N17584232: TP1.1 U1.T22(SPI0_D0/GPIO)

Not connected (* = marked no-connect by the designer): J1 35* 37* 38* 39* 40*; J2 7* 8*; J20 10 11 12 13 14 15 16 17 21 23 25 27 29 31 33 36 38 40 41 43 44 45 46 49 51 53 55 57 59 61 65 67 69 71 73 74 75 78 79 80 81 82 84 85 86 88 90 91 93 94 96 98 99 100; R20 2(P2)*; R23 3(SENS1)* 4(SENS2)*; R24 3(SENS1)* 4(SENS2)*; R59 1(P1)*; U1 A6(GPMC_AD3/MMC1_DAT3) AA7(EP_PIO_10/GPIO) AA9(EP_PIO_6/GPIO) AA10(EP_PIO_3/GPIO) AA19(CAM0_DATA9) AB6(EP_EVENT) AB7(EP_PIO_15/GPIO) AB9(TEST_TP0) AB10(EP_PIO_2/GPIO) AB19(CAM0_DATA8) AC5(EP_PIO_14/GPIO) AC6(EP_PIO_11/GPIO) AC7(TEST_TP2) AC9(EP_PIO_8/GPIO) AC10(EP_PIO_1/GPIO) AC12(EP_PIO_0/GPIO) AC18(CAM0_FIELD) AC21(CAM1_DATA1) AC25(CAM1_FIELD) AD1(TEMP_DIODE_P) AD2(TEMP_DIODE_N) AD7(TPM_PMIC_EN) AD10(TM_TESTOUT) AD11(CTPM_TESTOUT) AD17(CAM0_WEN) AE7(TPM_WAKEUP) AE8(PMU_HIBZ) AE9(NC) AE10(PMU_PORZ) AE11(XI_32K) AE12(XO_32K) AE21(CAM1_PCLK) B6(GPMC_AD2/MMC1_DAT2) D20(VDD_MPU_MON) D25(PLAT_MTST0) E25(PLAT_MTST4) F23(PLAT_MTST3) F24(PLAT_MTST1) G20(PLAT_MTST2) H19(NC) H20(CLKREQ)* H21(TESTOUT) N25(PLAT_STST3/GPIO) U22(USB1_CE) W10(TEST_TP1) W22(USB0_CE) Y6(TEST_TP3) Y7(EP_PIO_9/GPIO) Y10(EP_PIO_7/GPIO); U2 1(NC)*; U3 6(IN_LS3)* 7(LS3)* 10(PFOn)* 26(GPIO3) 28(RSV1)* 29(RSV2)* 32(IN_LS2)* 33(LS2)*; U5 3(~{RESET})* 4(NC4)* 5(NC5)* 6(NC6)* 11(NC11)* 12(NC12)* 13(NC13)* 14(NC14)*; U10 4(NC1)* 9(NC2)*; U26 5(NC)*; U29 3(ID)* 5(NC)*; U53 6(B2); Y1 2(NC0)* 4(NC1)*; Y2 2* 3*

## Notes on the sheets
sheet 10
- USB1 Port
sheet 11
- USB0 Port
sheet 12
- Key Pad
- Status LED's
sheet 13
- SD/MMC0 Connector
sheet 14
- LCD Module
- BackLight Power
sheet 15
- User Interrupt Switch
- Warm Reset Switch
sheet 18
- Main Power Input
- Test Only
- Coin Cell
  Connection
